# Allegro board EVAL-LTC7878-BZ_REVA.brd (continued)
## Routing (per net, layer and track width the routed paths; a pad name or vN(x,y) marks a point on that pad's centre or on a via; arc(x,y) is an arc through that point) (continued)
INTVCC_1: length 46.6
  TOP w0.254: v2(95.5,255.14) 95.81,255.14 R27.2 ; C21.1 v2(91.06,259.08) 91.19,259.21 91.19,260.22 91.97,261.01 U1.9 ; R26.2 106.05,259.52 106.05,259.84 v2(106.17,259.97) 106.06,260.08 106.06,260.44 R25.2 ; v2(78.87,258.32) TP14.1
  LAYER_6 w0.254: v2(78.87,258.32) 83.63,253.56 91.12,253.56 92.17,254.6 92.17,255.14 ; v2(106.17,259.97) 106.17,259.71 104.9,258.44 95,258.44 94.74,258.7 91.82,258.7 91.44,259.08 v2(91.06,259.08) 91.06,256.67 92.17,255.55 92.17,255.14 ; 92.17,255.14 v2(95.5,255.14)
INTVCC_2: length 47.1
  TOP w0.254: R57.2 95.81,194.18 v2(95.5,194.18) ; R55.2 106.06,199.48 106.06,199.12 v2(106.17,199.01) 106.05,198.88 106.05,198.56 R56.2 ; C54.1 v2(91.06,198.12) 91.19,198.25 91.19,199.39 91.84,200.05 U2.9 ; v2(78.87,197.36) TP39.1
  LAYER_6 w0.254: 91.95,194.18 91.95,194.56 91.06,195.45 v2(91.06,198.12) 91.82,198.12 92.2,197.74 94.61,197.74 94.93,197.42 104.97,197.42 106.17,198.63 v2(106.17,199.01) ; 91.95,194.18 91.95,193.55 90.68,192.28 83.95,192.28 v2(78.87,197.36) ; 91.95,194.18 v2(95.5,194.18)
INTVCC_3: length 46.9
  TOP w0.254: C87.1 v2(91.06,137.16) 91.06,137.35 91.19,137.48 91.19,138.43 91.84,139.09 U3.9 ; R91.2 106.06,138.52 106.06,138.16 v2(106.17,138.05) 106.05,137.92 106.05,137.6 R92.2 ; v2(78.87,136.4) TP48.1 ; v2(95.5,133.22) 95.81,133.22 R93.2
  LAYER_6 w0.254: v2(95.5,133.22) 91.95,133.22 ; 91.95,133.22 91.95,132.72 90.81,131.57 83.69,131.57 v2(78.87,136.4) ; 91.95,133.22 91.95,133.86 91.06,134.75 v2(91.06,137.16) 91.69,137.16 92.08,136.78 94.61,136.78 94.87,136.53 105.28,136.53 106.17,137.41 v2(106.17,138.05)
INTVCC_4: length 46.3
  TOP w0.254: v2(78.87,75.44) TP65.1 ; R125.2 106.05,76.64 106.05,76.96 v2(106.17,77.09) 106.06,77.2 106.06,77.56 R124.2 ; R126.2 95.81,72.26 v2(95.5,72.26) ; C120.1 v2(91.06,76.2) 91.06,76.26 91.19,76.39 91.19,77.47 91.84,78.13 U4.9
  LAYER_6 w0.254: 91.95,72.26 v2(95.5,72.26) ; 91.95,72.26 91.95,72.64 91.06,73.53 v2(91.06,76.2) 91.57,76.2 91.95,75.82 94.61,75.82 94.87,75.56 105.09,75.56 106.17,76.64 v2(106.17,77.09) ; 91.95,72.26 91.95,71.75 91.31,71.12 83.19,71.12 v2(78.87,75.44)
INTVCC_5: length 46.9
  TOP w0.254: C153.1 v2(91.06,15.24) 91.06,15.43 91.19,15.56 91.19,16.51 91.84,17.17 U5.9 ; R158.2 106.05,15.68 106.05,16 v2(106.17,16.13) 106.06,16.24 106.06,16.6 R157.2 ; v2(95.5,11.3) 95.81,11.3 R159.2 ; v2(78.87,14.48) TP82.1
  LAYER_6 w0.254: v2(95.5,11.3) 91.95,11.3 ; 91.95,11.3 91.95,10.79 90.61,9.46 83.88,9.46 v2(78.87,14.48) ; 91.95,11.3 91.95,11.75 91.06,12.64 v2(91.06,15.24) 92.08,15.24 92.33,14.99 94.49,14.99 94.87,14.61 105.09,14.61 106.17,15.68 v2(106.17,16.13)
ITH_1: length 27.3
  TOP w0.254: U1.22 98.27,258.09 99.06,257.3 v2(99.06,257.05) C14.1 ; v2(115.44,252.73) TP10.1 R4.1 ; R12.1 R11.1 98.04,255.37 99.06,256.39
  LAYER_6 w0.254: v2(99.06,257.05) 103.38,252.73 v2(115.44,252.73)
ITH_2: length 101.7
  TOP w0.254: 99.06,195.43 98.04,194.41 R41.1 R42.1 ; C47.1 v2(99.06,196.09) 99.06,196.34 98.27,197.13 U2.22 ; R174.1 TP35.1 v2(115.44,191.77) ; R4.2 v2(121.16,252.73)
  LAYER_5 w0.254: v2(115.44,191.77) 115.44,194.56 132.72,211.84 132.72,235.08 120.14,247.65 120.14,251.71 v2(121.16,252.73)
  LAYER_6 w0.254: v2(115.44,191.77) 103.38,191.77 v2(99.06,196.09)
ITH_3: length 106.9
  TOP w0.254: R174.2 v2(121.16,191.77) ; 99.06,134.47 98.04,133.45 R77.1 R78.1 ; C80.1 v2(99.06,135.13) 99.06,135.38 98.27,136.17 U3.22 ; R179.1 TP27.1 v2(115.44,130.18)
  LAYER_5 w0.254: v2(121.16,191.77) 120.02,190.63 120.02,186.31 132.72,173.61 132.72,154.18 126.75,148.21 119.51,148.21 116.59,145.29 116.59,134.62 115.44,133.48 v2(115.44,130.18)
  LAYER_6 w0.254: v2(115.44,130.18) 104.01,130.18 v2(99.06,135.13)
ITH_4: length 101.8
  TOP w0.254: C113.1 v2(99.06,74.17) 99.06,74.42 98.27,75.21 U4.22 ; R111.1 R110.1 98.04,72.49 99.06,73.51 ; v2(115.44,69.22) TP61.1 R184.1 ; R179.2 v2(121.16,130.18)
  LAYER_5 w0.254: v2(115.44,69.22) 115.44,72.64 116.46,73.66 116.46,74.93 132.72,91.19 132.72,112.27 120.27,124.71 120.27,125.98 121.16,126.87 v2(121.16,130.18)
  LAYER_6 w0.254: v2(115.44,69.22) 104.01,69.22 v2(99.06,74.17)
ITH_5: length 96
  TOP w0.254: U5.22 98.27,14.25 99.06,13.46 v2(99.06,13.21) C146.1 ; R144.1 R143.1 98.04,11.53 99.06,12.55 ; TP78.1 v2(115.44,10.16) ; R184.2 v2(121.16,69.22)
  LAYER_5 w0.254: v2(121.16,69.22) 121.16,66.29 120.14,65.28 120.14,63.75 132.72,51.18 132.72,30.61 115.44,13.34 v2(115.44,10.16)
  LAYER_6 w0.254: v2(115.44,10.16) 102.11,10.16 v2(99.06,13.21)
OUT1: length 174.5
  TOP w0.254: v2(104.46,262.32) 104.27,262.51 R1.1 ; U7.5 134.75,136.39 v2(134.75,136.4)
  LAYER_5 w0.254: v2(104.46,262.32) 107.25,262.32 107.82,261.75 121.79,261.75 140.97,242.57 140.97,156.21 134.24,149.48 134.24,144.27 133.1,143.13 126.49,143.13 122.78,139.42 JP5.8
  LAYER_6 w0.254: JP5.8 131.73,139.42 v2(134.75,136.4)
OUT2: length 97.2
  TOP w0.254: v2(104.46,201.36) 104.27,201.55 R171.1 ; U7.6 136.77,136.89 v2(137.54,137.67)
  LAYER_4 w0.254: v2(104.46,201.36) 117.67,201.36 137.92,181.1 142.49,181.1 144.78,178.82 144.78,144.27 138.18,137.67 v2(137.54,137.67)
OUT3: length 37.9
  TOP w0.254: U7.7 133.2,137.39 v2(132.72,136.91) ; v2(104.46,140.4) 104.27,140.59 R176.1
  LAYER_4 w0.254: v2(132.72,136.91) 131.7,136.91 131.44,136.65 131.44,134.49 130.3,133.35 124.71,133.35 121.16,136.91 113.79,136.91 110.3,140.4 v2(104.46,140.4)
OUT4: length 95.1
  TOP w0.254: R181.1 104.27,79.63 v2(104.46,79.44) ; v2(134.11,138.68) 134.9,137.89 U7.8
  LAYER_4 w0.254: v2(104.46,79.44) 111.44,79.44 126.62,94.61 139.57,94.61 142.11,97.16 142.11,128.65 139.32,131.44 135.64,131.44 133.73,133.35 133.73,138.3 v2(134.11,138.68)
OUT5: length 152.6
  TOP w0.254: v2(104.46,18.48) 104.27,18.67 R186.1 ; U7.9 v2(130.24,137.89)
  LAYER_4 w0.254: v2(104.46,18.48) 111.19,18.48 128.02,35.31 128.02,39.5 129.41,40.89 129.41,50.67 143.19,64.45 143.19,129.41 137.73,134.87 136.91,134.87 135.76,136.02 135.76,138.94 134.87,139.83 132.18,139.83 v2(130.24,137.89)
RUN_1: length 90.3
  TOP w0.254: R2.1 87.07,257.99 v1(87,258.06) ; U1.10 92.23,260.5 91.69,259.97 91.69,258.95 90.73,257.99 C13.1
  LAYER_4 w0.254: TP5.1 7.49,266.83 68.71,266.83 74.55,260.99 v2(78.17,260.99)
  LAYER_6 w0.254: v1(87,258.06) 84.07,260.99 v2(78.17,260.99)
RUN_2: length 177.2
  TOP w0.254: 87.5,256.26 v1(87.5,256.29) R2.2 ; C46.1 90.73,197.03 91.69,197.99 91.69,199.14 92.1,199.54 U2.10 ; v1(87,197.1) 87.07,197.03 R172.1
  LAYER_4 w0.254: TP30.1 8.45,222.88 31.31,200.03 v2(78.1,200.03)
  LAYER_5 w0.254: v1(87.5,256.29) 85.34,256.29 83.82,254.76 83.82,249.94 66.8,232.92 66.8,212.98 82.68,197.1 v1(87,197.1)
  LAYER_6 w0.254: v1(87,197.1) 84.07,200.03 v2(78.1,200.03)
RUN_3: length 186.9
  TOP w0.254: v1(87,136.14) 87.07,136.07 R177.1 ; R172.2 v1(87.5,195.33) 87.5,195.3 ; U3.10 92.17,138.58 91.69,138.11 91.69,137.03 91.09,136.43 90.91,136.43 C79.1
  LAYER_4 w0.254: v2(78.11,139.06) 49.78,139.06 9.4,98.68 7.87,98.68 TP2.1
  LAYER_5 w0.254: v1(87,136.14) 82.55,136.14 66.8,151.89 66.8,171.2 83.95,188.34 83.95,194.44 84.84,195.33 v1(87.5,195.33)
  LAYER_6 w0.254: v1(87,136.14) 87,138.05 85.98,139.06 v2(78.11,139.06)
RUN_4: length 173.9
  TOP w0.254: R182.1 87.07,75.11 v1(87,75.18) ; U4.10 92.1,77.62 91.69,77.22 91.69,76.07 90.73,75.11 C112.1 ; R177.2 v1(87.5,134.37) 87.5,134.34
  LAYER_4 w0.254: TP56.1 7.11,62.99 15.37,62.99 30.48,78.11 v2(78.11,78.11)
  LAYER_5 w0.254: v1(87,75.18) 82.55,75.18 66.8,90.93 66.8,114.43 86.74,134.37 v1(87.5,134.37)
  LAYER_6 w0.254: v2(78.11,78.11) 84.07,78.11 v1(87,75.18)
RUN_5: length 174.2
  TOP w0.254: 87.5,73.38 v1(87.5,73.41) R182.2 ; U5.10 92.1,16.66 91.69,16.26 91.69,15.11 91.06,14.48 90.81,14.48 90.55,14.22 C145.1 ; v1(87.76,14.1) 88.46,14.1 R138.2
  LAYER_4 w0.254: TP73.1 63.25,27.94 74.04,17.14 v2(78.17,17.14)
  LAYER_5 w0.254: v1(87.76,14.1) 82.68,14.1 66.8,29.97 66.8,50.29 83.95,67.44 83.95,71.88 85.47,73.41 v1(87.5,73.41)
  LAYER_6 w0.254: v1(87.76,14.1) 84.71,17.14 v2(78.17,17.14)
SS_1: length 29.6
  TOP w0.254: R3.1 TP9.1 v2(115.44,248.28) ; C11.1 v2(97.03,257.05) 97.03,257.56 97.27,257.8 U1.20
  LAYER_6 w0.254: v2(97.03,257.05) 98.04,256.03 98.04,254.13 103.89,248.28 v2(115.44,248.28)
SS_2: length 104.7
  TOP w0.254: R3.2 v2(121.16,248.28) ; C44.1 v2(97.03,196.09) 97.03,196.6 97.27,196.84 U2.20 ; v2(115.44,186.69) TP34.1 R173.1
  LAYER_5 w0.254: v2(115.44,186.69) 115.44,190.25 116.59,191.39 116.59,194.06 133.73,211.2 133.73,235.71 v2(121.16,248.28)
  LAYER_6 w0.254: v2(115.44,186.69) 104.78,186.69 98.04,193.42 98.04,195.07 v2(97.03,196.09)
SS_3: length 109.3
  TOP w0.254: U3.20 97.27,135.88 97.03,135.64 v2(97.03,135.13) C77.1 ; R178.1 TP26.1 v2(115.44,125.09) ; R173.2 v2(121.16,186.69)
  LAYER_5 w0.254: v2(121.16,186.69) 133.73,174.12 133.73,153.67 127.25,147.19 119.89,147.19 117.73,145.03 117.73,134.24 116.59,133.1 116.59,129.67 115.44,128.52 v2(115.44,125.09)
  LAYER_6 w0.254: v2(97.03,135.13) 98.04,134.11 98.04,132.46 105.41,125.09 v2(115.44,125.09)
SS_4: length 104.7
  TOP w0.254: C110.1 v2(97.03,74.17) 97.03,74.68 97.27,74.92 U4.20 ; v2(115.44,64.14) TP60.1 R183.1 ; R178.2 v2(121.16,125.09)
  LAYER_5 w0.254: v2(121.16,125.09) 121.41,125.09 133.73,112.78 133.73,90.81 117.47,74.55 117.47,73.28 116.46,72.26 116.46,68.96 115.44,67.94 v2(115.44,64.14)
  LAYER_6 w0.254: v2(115.44,64.14) 105.03,64.14 98.04,71.12 98.04,73.15 v2(97.03,74.17)
SS_5: length 98.5
  TOP w0.254: C143.1 v2(97.03,13.21) 97.03,13.72 97.27,13.96 U5.20 ; TP77.1 v2(115.44,5.08) ; R183.2 v2(121.16,64.14)
  LAYER_5 w0.254: v2(115.44,5.08) 115.44,8.64 116.59,9.78 116.59,12.95 133.73,30.1 133.73,51.56 v2(121.16,64.14)
  LAYER_6 w0.254: v2(97.03,13.21) 98.04,12.19 98.04,10.29 103.25,5.08 v2(115.44,5.08)
SYNC_1: length 83.1
  TOP w0.254: U1.30 101.48,262.01 v2(101.79,262.32) 101.98,262.51 R1.2
  LAYER_4 w0.254: TP7.1 177.16,265.43 v2(115.19,265.43)
  LAYER_6 w0.254: v2(101.79,262.32) 103.12,263.65 106.87,263.65 107.7,264.48 114.24,264.48 v2(115.19,265.43)
SYNC_2: length 90.6
  TOP w0.254: U2.30 101.48,201.05 v2(101.79,201.36) 101.98,201.55 R171.2
  LAYER_4 w0.254: TP32.1 173.23,216.41 130.24,216.41 120.04,206.21 v2(120.04,204.47)
  LAYER_6 w0.254: v2(120.04,204.47) 119.21,203.64 107.7,203.64 106.81,202.76 103.19,202.76 v2(101.79,201.36)
SYNC_3: length 100.2
  TOP w0.254: U3.30 101.48,140.09 v2(101.79,140.4) 101.98,140.59 R176.2
  LAYER_4 w0.254: v2(144.4,131.19) 144.91,131.19 TP23.1
  LAYER_6 w0.254: v2(101.79,140.4) 102.04,140.4 103.5,141.86 109.98,141.86 114.05,137.79 120.14,137.79 126.75,131.19 v2(144.4,131.19)
SYNC_4: length 89.3
  TOP w0.254: U4.30 101.48,79.13 v2(101.79,79.44) 101.98,79.63 R181.2
  LAYER_5 w0.254: v2(124.33,78.61) 162.56,78.61 TP58.1
  LAYER_6 w0.254: v2(124.33,78.61) 117.54,78.61 115.32,80.84 103.19,80.84 v2(101.79,79.44)
SYNC_5: length 84.6
  TOP w0.254: U5.30 101.48,18.17 v2(101.79,18.48) 101.98,18.67 R186.2
  LAYER_4 w0.254: TP75.1 123.07,27.81 v2(116.85,21.59)
  LAYER_6 w0.254: v2(116.85,21.59) 108.84,21.59 107.06,19.81 103.12,19.81 v2(101.79,18.48)
UNNAMED_1_ADLTC7878V2_I139_BG1: length 27.7
  TOP w0.254: v1(92.84,265.81) 92.84,265.01 U1.1 ; R10.2 v1(72.64,276.73)
  LAYER_4 w0.508: v1(92.84,265.81) 92.33,266.32 92.33,268.1 89.15,271.27 77.47,271.27 72.64,276.1 v1(72.64,276.73)
UNNAMED_1_ADLTC7878V2_I139_BG2: length 38.1
  TOP w0.254: R28.2 v1(106.81,276.73) ; U1.12 92.94,259.5 92.84,259.4
  TOP w0.381: 92.84,259.4 v1(92.84,257.68)
  LAYER_4 w0.508: v1(92.84,257.68) 92.84,256.16 95.38,253.62 99.69,253.62 102.87,256.79 102.87,265.43 106.81,269.37 v1(106.81,276.73)
UNNAMED_1_ADLTC7878V2_I139_BOOST1: length 2
  TOP w0.254: C16.1 94.77,267.12 U1.46
UNNAMED_1_ADLTC7878V2_I139_BOOST2: length 2.7
  TOP w0.254: C19.2 94.77,257.51 U1.15
UNNAMED_1_ADLTC7878V2_I139_CSN: length 6.4
  TOP w0.254: TP11.1 103.76,266.64 R29.1 102.62,266.57 100.55,264.5 U1.35
UNNAMED_1_ADLTC7878V2_I139_CSP: length 2.8
  TOP w0.254: TP16.1 101.85,264.92 100.94,264.01 U1.34
UNNAMED_1_ADLTC7878V2_I139_EXTVCC: length 16.1
  TOP w0.254: TP12.1 v2(78.99,263.14) ; U1.8 90.19,261.5 C20.1
  LAYER_6 w0.254: v2(91,262) 88.65,262 87.5,263.14 v2(78.99,263.14)
UNNAMED_1_ADLTC7878V2_I139_FREQ: length 2.8
  TOP w0.254: R18.1 101.98,261.49 101.49,261.01 U1.28
UNNAMED_1_ADLTC7878V2_I139_ISNSD: length 3.9
  TOP w0.254: U1.43 96.27,266.57 95.76,267.08 95.76,268.22 v2(95.5,268.48) 95.5,268.8 C17.1
  BOTTOM w0.254: C17.1 95.5,268.8 v2(95.5,268.48)
UNNAMED_1_ADLTC7878V2_I139_ISNSN: length 7.3
  TOP w0.254: C18.2 98.22,268.68 97.79,269.11 R16.2 R23.2 ; C18.2 v2(97.66,267.72) ; C18.2 97.27,266.76 U1.41
  BOTTOM w0.254: 96.51,267.84 R21.2 96.7,267.72 v2(97.66,267.72)
UNNAMED_1_ADLTC7878V2_I139_ISNSP: length 6.3
  TOP w0.254: 96.6,268.84 C18.1 96.77,267.54 U1.42 ; 96.6,268.84 96.7,268.73 v2(97.03,268.73) ; 96.6,268.84 C17.2 96.58,269.89 R19.2 R13.2
  BOTTOM w0.254: C17.2 96.7,268.73 v2(97.03,268.73)
UNNAMED_1_ADLTC7878V2_I139_ITHB: length 2.4
  TOP w0.254: R11.2 98.04,257.56 97.77,257.83 U1.21
UNNAMED_1_ADLTC7878V2_I139_MODE: length 6.1
  TOP w0.254: R22.1 v2(101.79,259.46) 101.26,259.46 100.71,260.01 U1.26 ; R26.1 v2(104.55,259.46)
  LAYER_6 w0.254: v2(101.79,259.46) 101.85,259.4 104.48,259.4 v2(104.55,259.46)
UNNAMED_1_ADLTC7878V2_I139_PGOOD: length 24.9
  TOP w0.254: U1.19 96.77,258.06 96.01,257.3 v2(96.01,257.05) R27.1 ; v2(78.87,254.63) TP15.1
  LAYER_6 w0.254: v2(96.01,257.05) 96.01,256.6 96.27,256.35 96.27,255.02 93.73,252.48 81.03,252.48 v2(78.87,254.63)
UNNAMED_1_ADLTC7878V2_I139_PHASMD: length 6.2
  TOP w0.254: 101.88,260.5 102.08,260.5 ; 101.88,260.5 101.85,260.48 ; 101.88,260.5 U1.27 ; 101.85,260.48 v2(101.79,260.48) ; 101.85,260.48 R24.1 ; R25.1 v2(104.55,260.48)
  LAYER_6 w0.254: v2(104.55,260.48) 104.48,260.54 101.85,260.54 v2(101.79,260.48)
UNNAMED_1_ADLTC7878V2_I139_SETCUR: length 3
  TOP w0.254: R20.1 102.11,263.52 101.09,262.5 U1.31
UNNAMED_1_ADLTC7878V2_I139_SW1: length 48.9
  TOP w0.254: R13.1 95.07,271.07 95,271.14 v1(94.87,271.14) ; R14.1 v1(82.55,281.05) ; C16.2 95.27,267.75 U1.45 ; C16.2 93.92,268.66 93.85,268.73 v1(93.6,268.73) ; C16.2 94.37,268.66
  LAYER_4 w0.508: v1(93.6,268.73) 89.28,273.05 86.36,273.05 80.01,279.4 80.01,283.21 79.5,283.72 v4(78.61,283.72)
  LAYER_6 w0.254: v1(82.55,281.05) 82.93,280.67 82.93,275.59 83.95,274.57 91.95,274.57 94.87,271.65 v1(94.87,271.14)
  vias: v4(74.8,283.72) v4(74.8,282.45) v4(74.8,281.18) v4(74.8,279.91) v4(76.07,283.72) v4(76.07,282.45) v4(76.07,281.18) v4(76.07,279.91) v4(77.34,283.72) v4(77.34,282.45) v4(77.34,281.18) v4(77.34,279.91) v4(78.61,282.45) v4(78.61,281.18) v4(78.61,279.91)
UNNAMED_1_ADLTC7878V2_I139_SW2: length 51.9
  TOP w0.254: U1.16 95.27,256.89 C19.1 ; L1.2 98.7,283.23 v1(98.68,283.21) ; R23.1 v1(99.06,271.78)
  TOP w0.508: C19.1 94.92,256.09 v1(94.87,256.03)
  LAYER_4 w0.508: v4(108.58,280.67) 107.89,280.67 104.65,277.43 104.65,269.88 99.89,265.11 99.89,260.03 98.17,258.32 95.76,258.32 94.87,257.43 v1(94.87,256.03)
  LAYER_6 w0.254: v1(98.68,283.21) 96.77,281.31 96.77,277.11 98.04,275.84 98.04,273.18 99.06,272.16 v1(99.06,271.78)
  vias: v3(99.19,280.16) v3(99.19,279.4) v3(99.95,280.16) v3(99.95,279.4) v3(100.71,280.16) v3(100.71,279.4) v3(101.47,280.16) v3(101.47,279.4) v3(102.23,280.16) v3(102.23,279.4) v4(108.58,284.48) v4(108.58,283.21) v4(108.58,281.94) v4(109.86,284.48) v4(109.86,283.21) v4(109.86,281.94) v4(109.86,280.67) v4(111.12,284.48) v4(111.12,283.21) v4(111.12,281.94) v4(111.12,280.67) v4(112.39,284.48) v4(112.39,283.21) v4(112.39,281.94) v4(112.39,280.67)
UNNAMED_1_ADLTC7878V2_I139_TG1: length 30.7
  TOP w0.254: v1(93.6,266.7) 93.85,266.7 94.27,266.28 U1.47
  LAYER_4 w0.508: v1(93.6,266.7) 94.49,267.59 94.49,269.11 89.53,274.07 86.74,274.07 80.9,279.91 80.9,286.89 v1(79.88,287.91)
UNNAMED_1_ADLTC7878V2_I139_TG2: length 43.9
  TOP w0.254: R30.2 v1(114.05,287.91) ; v1(93.98,257.68) 94.27,257.97 U1.14
  LAYER_4 w0.508: v1(93.98,257.68) 95.5,259.21 97.79,259.21 99.06,260.48 99.06,265.56 103.76,270.26 103.76,277.88 107.19,281.31 107.19,284.86 108.2,285.88 112.01,285.88 v1(114.05,287.91)
UNNAMED_1_ADLTC7878V2_I139_VIN: length 3.3
  TOP w0.254: C12.1 91.19,264.39 92.08,263.5 U1.4
UNNAMED_1_ADLTC7878V2_I139_VOUT: length 19.2
  TOP w0.254: R71.1 100.13,268.17 100.08,268.22 v1(99.69,268.22) 99.19,267.72 99.19,266.83 98.77,266.41 U1.38 ; R70.2 v2(88.77,260.1)
  LAYER_4 w0.254: v1(99.69,268.22) 97.79,266.32 95.38,266.32 92.33,263.27 92.33,261.87 91.31,260.86 89.53,260.86 v2(88.77,260.1)
UNNAMED_1_CAP_I38_N1: length 1
  TOP w0.254: R12.2 C15.1
UNNAMED_1_CAP_I100_N2: length 2
  TOP w0.254: R32.1 106.68,267.14 TP13.1
UNNAMED_1_IND_I92_N1: length 41.1
  TOP w0.254: R14.2 v1(83.82,281.05) ; R16.1 v1(97.79,271.78) ; v1(94.36,283.21) 94.34,283.23 L1.1 ; R19.1 v1(96.52,271.65)
  LAYER_6 w0.254: v1(94.36,283.21) 96.27,281.31 96.27,276.86 97.54,275.59 97.54,273.18 96.52,272.16 v1(96.52,271.65) ; v1(83.82,281.05) 83.44,280.67 83.44,275.84 84.2,275.08 92.2,275.08 95.38,271.91 95.38,271.53 96.01,270.89 97.28,270.89 97.79,271.4 v1(97.79,271.78)
  vias: v3(90.68,280.16) v3(90.68,279.4) v3(91.44,280.16) v3(91.44,279.4) v3(92.2,280.16) v3(92.2,279.4) v3(92.96,280.16) v3(92.96,279.4) v3(93.73,280.16) v3(93.73,279.4)
UNNAMED_1_NCTESTPAD_I113_N1: length 5.3
  TOP w0.254: R35.1 R34.2
  TOP w0.381: TP20.1 106.68,255.97 105.03,257.62 105.03,258.26 104.97,258.32 R34.2
UNNAMED_1_RES_I72_N1: length 7.7
  TOP w0.254: v1(79.25,286.26) 78.86,285.87 78.37,285.87
  LAYER_6 w0.508: v1(73.66,286.26) v1(79.25,286.26)
  BOTTOM w0.254: v1(73.66,286.26) 74.05,285.87 74.53,285.87
UNNAMED_1_RES_I73_N1: length 7.8
  TOP w0.254: v1(73.15,279.02) 73.15,279.38 72.61,279.92
  LAYER_6 w0.508: v1(73.15,284.61) v1(73.15,279.02)
  BOTTOM w0.254: v1(73.15,284.61) 72.61,284.06 72.61,283.76
UNNAMED_1_RES_I87_N1: length 7.9
  TOP w0.254: M3.4 112.99,278.68 v1(113.28,278.38)
  LAYER_6 w0.508: v1(107.57,278.38) v1(113.28,278.38)
  BOTTOM w0.254: M7.4 107.86,278.68 v1(107.57,278.38)
UNNAMED_1_RES_I115_N1: length 8.2
  TOP w0.254: M4.4 114.44,280.32 114.05,279.92 v1(114.05,279.78)
  LAYER_6 w0.508: v1(114.05,285.62) v1(114.05,279.78)
  BOTTOM w0.254: M8.4 114.44,285.23 v1(114.05,285.62)
UNNAMED_2_ADLTC7878V2_I124_BG1: length 27.4
  TOP w0.254: R40.2 v1(72.64,215.77) ; U2.1 92.84,204.05 v1(92.84,204.85)
  LAYER_4 w0.508: v1(72.64,215.77) 77.85,210.57 88.9,210.57 92.33,207.14 92.33,205.36 v1(92.84,204.85)
UNNAMED_2_ADLTC7878V2_I124_BG2: length 38.3
  TOP w0.254: 92.84,198.5 92.88,198.54 U2.12 ; R58.2 v1(106.81,215.77)
  TOP w0.381: v1(92.84,196.72) 92.84,198.5
  LAYER_4 w0.508: v1(106.81,215.77) 106.81,208.28 102.87,204.34 102.87,195.58 99.95,192.66 95.38,192.66 92.84,195.2 v1(92.84,196.72)
UNNAMED_2_ADLTC7878V2_I124_BOOST1: length 2
  TOP w0.254: U2.46 94.77,206.16 C49.1
UNNAMED_2_ADLTC7878V2_I124_BOOST2: length 2.7
  TOP w0.254: C52.2 94.77,196.55 U2.15
UNNAMED_2_ADLTC7878V2_I124_CSN: length 6.4
  TOP w0.254: U2.35 100.55,203.54 102.49,205.49 103.7,205.49 R59.1 103.83,207.19 TP36.1
UNNAMED_2_ADLTC7878V2_I124_CSP: length 2.9
  TOP w0.254: TP41.1 102.23,203.71 101.47,203.71 100.81,203.05 U2.34
UNNAMED_2_ADLTC7878V2_I124_EXTVCC: length 16.1
  TOP w0.254: C53.1 90.19,200.54 U2.8 ; TP37.1 v2(78.99,202.18)
  LAYER_6 w0.254: v2(78.99,202.18) 87.25,202.18 88.39,201.04 v2(91,201.04)
UNNAMED_2_ADLTC7878V2_I124_FREQ: length 2.8
  TOP w0.254: U2.28 101.49,200.05 101.98,200.53 R48.1
UNNAMED_2_ADLTC7878V2_I124_ISNSD: length 3.9
  TOP w0.254: C50.1 95.5,207.84 v2(95.5,207.52) 95.76,207.26 95.76,206.12 96.27,205.61 U2.43
  BOTTOM w0.254: C50.1 95.5,207.84 v2(95.5,207.52)
UNNAMED_2_ADLTC7878V2_I124_ISNSN: length 7.3
  TOP w0.254: R53.2 R46.2 97.79,208.15 98.22,207.72 C51.2 ; C51.2 97.27,205.8 U2.41 ; C51.2 v2(97.66,206.76)
  BOTTOM w0.254: 96.51,206.88 R51.2 97.54,206.88 v2(97.66,206.76)
UNNAMED_2_ADLTC7878V2_I124_ISNSP: length 6.3
  TOP w0.254: 96.6,207.88 C51.1 96.77,206.58 U2.42 ; 96.6,207.88 96.7,207.77 v2(97.03,207.77) ; 96.6,207.88 C50.2 96.58,208.93 R49.2 R43.2
  BOTTOM w0.254: C50.2 96.7,207.77 v2(97.03,207.77)
UNNAMED_2_ADLTC7878V2_I124_ITHB: length 2.4
  TOP w0.254: R41.2 98.04,196.6 97.77,196.87 U2.21
UNNAMED_2_ADLTC7878V2_I124_MODE: length 6.1
  TOP w0.254: U2.26 100.71,199.05 101.26,198.5 v2(101.79,198.5) R52.1 ; R56.1 v2(104.55,198.5)
  LAYER_6 w0.254: v2(104.55,198.5) 104.48,198.44 101.85,198.44 v2(101.79,198.5)
UNNAMED_2_ADLTC7878V2_I124_PGOOD: length 25.4
  TOP w0.254: R57.1 v2(96.01,196.09) 96.01,196.34 96.77,197.1 U2.19 ; v2(78.87,193.68) TP40.1
  LAYER_6 w0.254: v2(96.01,196.09) 96.01,195.71 96.39,195.33 96.39,194.18 93.22,191.01 81.53,191.01 v2(78.87,193.68)
UNNAMED_2_ADLTC7878V2_I124_PHASMD: length 6.2
  TOP w0.254: 102.08,199.54 101.82,199.54 ; 101.82,199.54 U2.27 ; 101.82,199.54 v2(101.79,199.52) R54.1 ; R55.1 v2(104.55,199.52)
  LAYER_6 w0.254: v2(104.55,199.52) 104.48,199.58 101.85,199.58 v2(101.79,199.52)
UNNAMED_2_ADLTC7878V2_I124_SETCUR: length 3
  TOP w0.254: U2.31 101.09,201.54 102.11,202.56 R50.1
UNNAMED_2_ADLTC7878V2_I124_SW1: length 48.9
  TOP w0.254: C49.2 95.27,206.79 U2.45 ; C49.2 93.92,207.7 93.85,207.77 v1(93.6,207.77) ; C49.2 94.37,207.7 ; R43.1 95.07,210.11 95,210.19 v1(94.87,210.19) ; R44.1 v1(82.55,220.09)
  LAYER_4 w0.508: v1(93.6,207.77) 89.28,212.09 86.36,212.09 79.88,218.57 79.88,222.38 79.5,222.76 v4(78.61,222.76)
  LAYER_6 w0.254: v1(94.87,210.19) 94.87,210.76 94.04,211.58 85.98,211.58 82.93,214.63 82.93,219.71 v1(82.55,220.09)
  vias: v4(74.8,222.76) v4(74.8,221.49) v4(74.8,220.22) v4(74.8,218.95) v4(76.07,222.76) v4(76.07,221.49) v4(76.07,220.22) v4(76.07,218.95) v4(77.34,222.76) v4(77.34,221.49) v4(77.34,220.22) v4(77.34,218.95) v4(78.61,221.49) v4(78.61,220.22) v4(78.61,218.95)
UNNAMED_2_ADLTC7878V2_I124_SW2: length 51.9
  TOP w0.254: U2.16 95.27,195.93 C52.1 ; L2.2 98.7,222.27 v1(98.68,222.25) ; R53.1 v1(99.06,210.82)
  TOP w0.508: v1(94.87,195.07) 94.92,195.13 C52.1
  LAYER_4 w0.508: v1(94.87,195.07) 94.87,196.47 95.76,197.36 98.17,197.36 99.89,199.07 99.89,204.03 104.65,208.79 104.65,216.47 107.89,219.71 v4(108.58,219.71)
  LAYER_6 w0.254: v1(98.68,222.25) 96.77,220.34 96.77,216.15 98.04,214.88 98.04,212.22 99.06,211.2 v1(99.06,210.82)
  vias: v3(99.19,219.2) v3(99.19,218.44) v3(99.95,219.2) v3(99.95,218.44) v3(100.71,219.2) v3(100.71,218.44) v3(101.47,219.2) v3(101.47,218.44) v3(102.23,219.2) v3(102.23,218.44) v4(108.58,223.52) v4(108.58,222.25) v4(108.58,220.98) v4(109.86,223.52) v4(109.86,222.25) v4(109.86,220.98) v4(109.86,219.71) v4(111.12,223.52) v4(111.12,222.25) v4(111.12,220.98) v4(111.12,219.71) v4(112.39,223.52) v4(112.39,222.25) v4(112.39,220.98) v4(112.39,219.71)
UNNAMED_2_ADLTC7878V2_I124_TG1: length 30.7
  TOP w0.254: v1(93.6,205.74) 93.85,205.74 94.27,205.32 U2.47
  LAYER_4 w0.508: v1(93.6,205.74) 93.6,206.25 94.49,207.14 94.49,208.15 89.66,212.98 86.87,212.98 80.9,218.95 80.9,225.93 v1(79.88,226.95)
UNNAMED_2_ADLTC7878V2_I124_TG2: length 44.1
  TOP w0.254: v1(93.98,196.72) 93.98,196.98 94.27,197.27 U2.14 ; R60.2 v1(114.05,226.95)
  LAYER_4 w0.508: v1(93.98,196.72) 93.98,196.98 95.25,198.25 97.79,198.25 99.06,199.52 99.06,204.47 103.76,209.17 103.76,216.92 107.19,220.34 107.19,223.9 108.2,224.92 112.01,224.92 v1(114.05,226.95)
UNNAMED_2_ADLTC7878V2_I124_VIN: length 3.3
  TOP w0.254: U2.4 92.08,202.54 91.19,203.43 C45.1
UNNAMED_2_ADLTC7878V2_I124_VOUT: length 19.2
  TOP w0.254: R67.2 v2(88.77,199.14) ; U2.38 98.77,205.45 99.19,205.87 99.19,206.76 v1(99.69,207.26) 100.08,207.26 100.13,207.21 R68.1
  LAYER_4 w0.254: v2(88.77,199.14) 89.66,200.03 91.69,200.03 92.84,201.17 92.84,202.44 95.89,205.49 97.92,205.49 v1(99.69,207.26)
UNNAMED_2_CAP_I32_N1: length 1
  TOP w0.254: R42.2 C48.1
UNNAMED_2_CAP_I92_N2: length 2
  TOP w0.254: TP38.1 106.68,206.18 R62.1
UNNAMED_2_IND_I83_N1: length 41.2
  TOP w0.254: L2.1 94.34,222.27 v1(94.36,222.25) ; R49.1 v1(96.52,210.69) ; R46.1 v1(97.79,210.82) ; R44.2 v1(83.82,220.09)
  LAYER_6 w0.254: v1(94.36,222.25) 96.27,220.34 96.27,215.9 97.54,214.63 97.54,212.22 96.52,211.2 v1(96.52,210.69) ; v1(83.82,220.09) 83.44,219.71 83.44,214.88 86.23,212.09 94.36,212.09 95.5,210.95 95.5,210.31 95.89,209.93 97.28,209.93 97.79,210.44 v1(97.79,210.82)
  vias: v3(90.68,219.2) v3(90.68,218.44) v3(91.44,219.2) v3(91.44,218.44) v3(92.2,219.2) v3(92.2,218.44) v3(92.96,219.2) v3(92.96,218.44) v3(93.73,219.2) v3(93.73,218.44)
UNNAMED_2_NCTESTPAD_I104_N1: length 5.3
  TOP w0.254: R65.1 R64.2
  TOP w0.381: R64.2 104.97,197.36 105.03,197.3 105.03,196.66 106.68,195.01 TP45.1
UNNAMED_2_RES_I63_N1: length 7.7
  TOP w0.254: v1(79.25,225.3) 78.86,224.91 78.37,224.91
  LAYER_6 w0.508: v1(73.66,225.3) v1(79.25,225.3)
  BOTTOM w0.254: 74.53,224.91 74.05,224.91 v1(73.66,225.3)
UNNAMED_2_RES_I64_N1: length 7.8
  TOP w0.254: 72.61,218.96 73.15,218.42 v1(73.15,218.06)
  LAYER_6 w0.508: v1(73.15,223.65) v1(73.15,218.06)
  BOTTOM w0.254: 72.61,222.8 72.61,223.1 v1(73.15,223.65)
UNNAMED_2_RES_I78_N1: length 7.9
  TOP w0.254: M11.4 112.99,217.72 v1(113.28,217.42)
  LAYER_6 w0.508: v1(107.57,217.42) v1(113.28,217.42)
  BOTTOM w0.254: M15.4 107.86,217.72 v1(107.57,217.42)
UNNAMED_2_RES_I106_N1: length 8.2
  TOP w0.254: M12.4 114.44,219.36 114.05,218.96 v1(114.05,218.82)
  LAYER_6 w0.508: v1(114.05,224.66) v1(114.05,218.82)
  BOTTOM w0.254: M16.4 114.44,224.27 v1(114.05,224.66)
UNNAMED_3_ADLTC7878V2_I47_BG1: length 27.7
  TOP w0.254: v1(92.84,143.89) 92.84,143.09 U3.1 ; R76.2 v1(72.64,154.81)
  LAYER_4 w0.508: v1(92.84,143.89) 92.33,144.4 92.33,146.3 89.41,149.22 77.72,149.22 72.64,154.31 v1(72.64,154.81)
UNNAMED_3_ADLTC7878V2_I47_BG2: length 38
  TOP w0.254: R95.2 v1(106.81,154.81) ; U3.12 92.88,137.58 92.84,137.54
  TOP w0.381: v1(92.84,135.76) 92.84,137.54
  LAYER_4 w0.508: v1(92.84,135.76) 92.84,134.24 95.38,131.7 99.44,131.7 102.87,135.13 102.87,143.51 106.81,147.45 v1(106.81,154.81)
UNNAMED_3_ADLTC7878V2_I47_BOOST1: length 2
  TOP w0.254: C82.1 94.77,145.2 U3.46
UNNAMED_3_ADLTC7878V2_I47_BOOST2: length 2.7
  TOP w0.254: C85.2 94.77,135.59 U3.15
UNNAMED_3_ADLTC7878V2_I47_CSN: length 6.4
  TOP w0.254: TP28.1 103.76,144.72 R96.1 102.62,144.65 100.55,142.58 U3.35
UNNAMED_3_ADLTC7878V2_I47_CSP: length 2.9
  TOP w0.254: U3.34 100.81,142.09 101.66,142.94 102.43,142.94 TP50.1
UNNAMED_3_ADLTC7878V2_I47_EXTVCC: length 16.1
  TOP w0.254: C86.1 90.19,139.58 U3.8 ; TP29.1 v2(78.99,141.22)
  LAYER_6 w0.254: v2(91,140.08) 88.39,140.08 87.25,141.22 v2(78.99,141.22)
UNNAMED_3_ADLTC7878V2_I47_FREQ: length 2.8
  TOP w0.254: R84.1 101.98,139.57 101.49,139.09 U3.28
UNNAMED_3_ADLTC7878V2_I47_ISNSD: length 3.9
  TOP w0.254: C83.1 95.5,146.88 v2(95.5,146.56) 95.76,146.3 95.76,145.16 96.27,144.65 U3.43
  BOTTOM w0.254: C83.1 95.45,146.61 v2(95.5,146.56)
UNNAMED_3_ADLTC7878V2_I47_ISNSN: length 7.3
  TOP w0.254: C84.2 97.27,144.84 U3.41 ; C84.2 98.22,146.76 97.79,147.19 R82.2 R89.2 ; C84.2 v2(97.66,145.8)
  BOTTOM w0.254: R87.2 97.54,145.92 v2(97.66,145.8)
UNNAMED_3_ADLTC7878V2_I47_ISNSP: length 6.3
  TOP w0.254: 96.6,146.92 C84.1 96.77,145.62 U3.42 ; 96.6,146.92 96.7,146.81 v2(97.03,146.81) ; 96.6,146.92 C83.2 96.58,147.97 R85.2 R79.2
  BOTTOM w0.254: v2(97.03,146.81) 96.7,146.81 C83.2
UNNAMED_3_ADLTC7878V2_I47_ITHB: length 2.4
  TOP w0.254: U3.21 97.77,135.91 98.04,135.64 R77.2
UNNAMED_3_ADLTC7878V2_I47_MODE: length 6.1
  TOP w0.254: U3.26 100.71,138.09 101.26,137.54 v2(101.79,137.54) R88.1 ; R92.1 v2(104.55,137.54)
  LAYER_6 w0.254: v2(104.55,137.54) 104.48,137.48 101.85,137.48 v2(101.79,137.54)
UNNAMED_3_ADLTC7878V2_I47_PGOOD: length 25.1
  TOP w0.254: v2(78.87,132.72) TP49.1 ; U3.19 96.77,136.14 96.01,135.38 v2(96.01,135.13) R93.1
  LAYER_6 w0.254: v2(78.87,132.72) 81.15,130.43 93.6,130.43 96.39,133.22 96.39,134.24 96.01,134.62 v2(96.01,135.13)
UNNAMED_3_ADLTC7878V2_I47_PHASMD: length 6.2
  TOP w0.254: 101.82,138.58 U3.27 ; 101.82,138.58 v2(101.79,138.56) R90.1 ; 101.82,138.58 102.08,138.58 ; R91.1 v2(104.55,138.56)
  LAYER_6 w0.254: v2(104.55,138.56) 104.48,138.62 101.85,138.62 v2(101.79,138.56)
UNNAMED_3_ADLTC7878V2_I47_SETCUR: length 3
  TOP w0.254: R86.1 102.11,141.6 101.09,140.58 U3.31
UNNAMED_3_ADLTC7878V2_I47_SW1: length 49
  TOP w0.254: C82.2 95.27,145.83 U3.45 ; C82.2 93.92,146.74 93.85,146.81 v1(93.6,146.81) ; C82.2 94.37,146.74 ; R79.1 95.07,149.15 95,149.22 v1(94.87,149.22) ; R80.1 v1(82.55,159.13)
  LAYER_4 w0.508: v4(78.61,161.8) 79.5,161.8 80.01,161.29 80.01,157.48 86.74,150.75 89.66,150.75 v1(93.6,146.81)
  LAYER_6 w0.254: v1(82.55,159.13) 82.93,158.75 82.93,153.67 83.95,152.65 92.08,152.65 94.87,149.86 v1(94.87,149.22)
  vias: v4(74.8,161.8) v4(74.8,160.53) v4(74.8,159.26) v4(74.8,157.99) v4(76.07,161.8) v4(76.07,160.53) v4(76.07,159.26) v4(76.07,157.99) v4(77.34,161.8) v4(77.34,160.53) v4(77.34,159.26) v4(77.34,157.99) v4(78.61,160.53) v4(78.61,159.26) v4(78.61,157.99)
UNNAMED_3_ADLTC7878V2_I47_SW2: length 52.2
  TOP w0.254: R89.1 v1(99.06,149.86) ; v1(98.68,161.29) 98.7,161.31 L3.2 ; U3.16 95.27,134.97 C85.1
  TOP w0.508: v1(94.87,134.11) 94.92,134.17 C85.1
  LAYER_4 w0.508: v4(108.58,158.75) 107.89,158.75 104.65,155.51 104.65,147.7 99.89,142.94 99.89,137.86 98.81,136.78 95.89,136.78 94.87,135.76 v1(94.87,134.11)
  LAYER_6 w0.254: v1(98.68,161.29) 96.77,159.38 96.77,155.19 98.04,153.92 98.04,151.13 99.06,150.11 v1(99.06,149.86)
  vias: v3(99.19,158.24) v3(99.19,157.48) v3(99.95,158.24) v3(99.95,157.48) v3(100.71,158.24) v3(100.71,157.48) v3(101.47,158.24) v3(101.47,157.48) v3(102.23,158.24) v3(102.23,157.48) v4(108.58,162.56) v4(108.58,161.29) v4(108.58,160.02) v4(109.86,162.56) v4(109.86,161.29) v4(109.86,160.02) v4(109.86,158.75) v4(111.12,162.56) v4(111.12,161.29) v4(111.12,160.02) v4(111.12,158.75) v4(112.39,162.56) v4(112.39,161.29) v4(112.39,160.02) v4(112.39,158.75)
UNNAMED_3_ADLTC7878V2_I47_TG1: length 30.8
  TOP w0.254: v1(93.6,144.78) 93.85,144.78 94.27,144.36 U3.47
  LAYER_4 w0.508: v1(93.6,144.78) 94.61,145.8 94.61,147.07 90.04,151.64 87.25,151.64 80.9,157.99 80.9,164.97 v1(79.88,165.99)
UNNAMED_3_ADLTC7878V2_I47_TG2: length 44.3
  TOP w0.254: U3.14 94.27,136.05 v1(93.98,135.76) ; R97.2 v1(114.05,165.99)
  LAYER_4 w0.508: v1(93.98,135.76) 93.98,136.14 95.5,137.67 98.42,137.67 99.06,138.3 99.06,143.38 103.76,148.08 103.76,155.96 107.19,159.38 107.19,162.94 108.2,163.96 112.01,163.96 v1(114.05,165.99)
UNNAMED_3_ADLTC7878V2_I47_VIN: length 3.3
  TOP w0.254: U3.4 92.08,141.58 91.19,142.47 C78.1
UNNAMED_3_ADLTC7878V2_I47_VOUT: length 19.2
  TOP w0.254: R98.1 100.13,146.25 100.08,146.3 v1(99.69,146.3) 99.19,145.8 99.19,144.91 98.77,144.49 U3.38 ; R94.2 v2(88.77,138.18)
  LAYER_4 w0.254: v1(99.69,146.3) 98.04,144.65 95.76,144.65 92.84,141.73 92.84,140.34 90.68,138.18 v2(88.77,138.18)
UNNAMED_3_CAP_I32_N1: length 1
  TOP w0.254: R78.2 C81.1
UNNAMED_3_CAP_I94_N2: length 2
  TOP w0.254: R100.1 106.68,145.22 TP47.1
UNNAMED_3_IND_I85_N1: length 41.2
  TOP w0.254: L3.1 94.34,161.31 v1(94.36,161.29) ; R82.1 v1(97.79,149.86) ; R80.2 v1(83.82,159.13) ; R85.1 v1(96.52,149.73)
  LAYER_6 w0.254: v1(96.52,149.73) 96.52,150.11 97.54,151.13 97.54,153.67 96.27,154.94 96.27,159.38 v1(94.36,161.29) ; v1(83.82,159.13) 83.44,158.75 83.44,153.92 84.2,153.16 92.46,153.16 95.5,150.11 95.5,149.48 96.01,148.97 97.28,148.97 97.79,149.48 v1(97.79,149.86)
  vias: v3(90.68,158.24) v3(90.68,157.48) v3(91.44,158.24) v3(91.44,157.48) v3(92.2,158.24) v3(92.2,157.48) v3(92.96,158.24) v3(92.96,157.48) v3(93.73,158.24) v3(93.73,157.48)
UNNAMED_3_NCTESTPAD_I107_N1: length 5.3
  TOP w0.254: R103.1 R102.2
  TOP w0.381: R102.2 104.97,136.4 105.03,136.34 105.03,135.7 106.68,134.05 TP54.1
UNNAMED_3_RES_I65_N1: length 7.7
  TOP w0.254: 78.37,163.95 78.86,163.95 v1(79.25,164.34)
  LAYER_6 w0.508: v1(73.66,164.34) v1(79.25,164.34)
  BOTTOM w0.254: 74.53,163.95 74.05,163.95 v1(73.66,164.34)
UNNAMED_3_RES_I66_N1: length 7.8
  TOP w0.254: v1(73.15,157.1) 73.15,157.46 72.61,158
  LAYER_6 w0.508: v1(73.15,162.69) v1(73.15,157.1)
  BOTTOM w0.254: 72.61,161.84 72.61,162.14 v1(73.15,162.69)
UNNAMED_3_RES_I80_N1: length 7.9
  TOP w0.254: v1(113.28,156.46) 112.99,156.76 M19.4
  LAYER_6 w0.508: v1(107.57,156.46) v1(113.28,156.46)
  BOTTOM w0.254: M23.4 107.86,156.76 v1(107.57,156.46)
UNNAMED_3_RES_I109_N1: length 8.2
  TOP w0.254: M20.4 114.44,158.4 114.05,158 v1(114.05,157.86)
  LAYER_6 w0.508: v1(114.05,163.7) v1(114.05,157.86)
  BOTTOM w0.254: v1(114.05,163.7) 114.44,163.31 M24.4
UNNAMED_4_ADLTC7878V2_I126_BG1: length 27.6
  TOP w0.254: v1(92.84,82.93) 92.84,82.13 U4.1 ; R109.2 v1(72.64,93.85)
  LAYER_4 w0.508: v1(92.84,82.93) 92.33,83.44 92.33,85.09 89.03,88.39 77.6,88.39 72.64,93.34 v1(72.64,93.85)
UNNAMED_4_ADLTC7878V2_I126_BG2: length 38
  TOP w0.254: R128.2 v1(106.81,93.85) ; U4.12 92.88,76.62 92.84,76.58
  TOP w0.381: v1(92.84,74.8) 92.84,76.58
  LAYER_4 w0.508: v1(92.84,74.8) 92.84,73.28 95.38,70.74 99.57,70.74 102.87,74.04 102.87,82.55 106.81,86.49 v1(106.81,93.85)
UNNAMED_4_ADLTC7878V2_I126_BOOST1: length 2
  TOP w0.254: C115.1 94.77,84.24 U4.46
UNNAMED_4_ADLTC7878V2_I126_BOOST2: length 2.7
  TOP w0.254: C118.2 94.77,74.63 U4.15
UNNAMED_4_ADLTC7878V2_I126_CSN: length 6.4
  TOP w0.254: U4.35 100.55,81.62 102.62,83.69 R129.1 103.76,83.76 TP62.1
UNNAMED_4_ADLTC7878V2_I126_CSP: length 2.9
  TOP w0.254: TP67.1 102.23,81.79 101.47,81.79 100.81,81.13 U4.34
UNNAMED_4_ADLTC7878V2_I126_EXTVCC: length 16.6
  TOP w0.254: U4.8 90.19,78.62 C119.1 ; TP63.1 v2(78.99,80.26)
  LAYER_6 w0.254: v2(78.99,80.26) 82.8,80.26 83.31,80.77 86.87,80.77 88.52,79.12 v2(91,79.12)
UNNAMED_4_ADLTC7878V2_I126_FREQ: length 2.8
  TOP w0.254: U4.28 101.49,78.13 101.98,78.61 R117.1
UNNAMED_4_ADLTC7878V2_I126_ISNSD: length 3.9
  TOP w0.254: U4.43 96.27,83.69 95.76,84.2 95.76,85.34 v2(95.5,85.6) 95.5,85.92 C116.1
  BOTTOM w0.254: C116.1 95.5,85.92 v2(95.5,85.6)
UNNAMED_4_ADLTC7878V2_I126_ISNSN: length 7.3
  TOP w0.254: v2(97.66,84.84) C117.2 ; C117.2 98.22,85.8 97.79,86.23 R115.2 R122.2 ; C117.2 97.27,83.88 U4.41
  BOTTOM w0.254: R120.2 97.54,84.96 v2(97.66,84.84)
UNNAMED_4_ADLTC7878V2_I126_ISNSP: length 6.3
  TOP w0.254: R112.2 R118.2 96.58,87.01 C116.2 96.6,85.96 ; U4.42 96.77,84.66 C117.1 96.6,85.96 ; 96.6,85.96 96.7,85.85 v2(97.03,85.85)
  BOTTOM w0.254: C116.2 96.7,85.85 v2(97.03,85.85)
UNNAMED_4_ADLTC7878V2_I126_ITHB: length 2.4
  TOP w0.254: R110.2 98.04,74.68 97.77,74.95 U4.21
UNNAMED_4_ADLTC7878V2_I126_MODE: length 6.1
  TOP w0.254: U4.26 100.71,77.13 101.26,76.58 v2(101.79,76.58) R121.1 ; R125.1 v2(104.55,76.58)
  LAYER_6 w0.254: v2(101.79,76.58) 101.85,76.52 104.48,76.52 v2(104.55,76.58)
UNNAMED_4_ADLTC7878V2_I126_PGOOD: length 24.2
  TOP w0.254: U4.19 96.77,75.18 96.01,74.42 v2(96.01,74.17) R126.1 ; v2(78.87,71.12) TP66.1
  LAYER_6 w0.254: v2(78.87,71.12) 79.88,70.1 94.11,70.1 96.39,72.39 96.39,73.41 96.01,73.79 v2(96.01,74.17)
UNNAMED_4_ADLTC7878V2_I126_PHASMD: length 6.2
  TOP w0.254: 101.82,77.62 U4.27 ; 101.82,77.62 v2(101.79,77.6) R123.1 ; 101.82,77.62 102.08,77.62 ; R124.1 v2(104.55,77.6)
  LAYER_6 w0.254: v2(104.55,77.6) 104.48,77.66 101.85,77.66 v2(101.79,77.6)
UNNAMED_4_ADLTC7878V2_I126_SETCUR: length 3
  TOP w0.254: R119.1 102.11,80.64 101.09,79.62 U4.31
UNNAMED_4_ADLTC7878V2_I126_SW1: length 48.8
  TOP w0.254: U4.45 95.27,84.87 C115.2 ; R113.1 v1(82.55,98.17) ; C115.2 94.37,85.78 ; C115.2 93.92,85.78 93.85,85.85 v1(93.6,85.85) ; R112.1 95.07,88.19 95,88.27 v1(94.87,88.27)
  LAYER_4 w0.508: v1(93.6,85.85) 89.53,89.92 86.61,89.92 80.01,96.52 80.01,100.33 79.5,100.84 v4(78.61,100.84)
  LAYER_6 w0.254: v1(94.87,88.27) 94.87,88.65 91.82,91.69 83.95,91.69 82.93,92.71 82.93,97.79 v1(82.55,98.17)
  vias: v4(74.8,100.84) v4(74.8,99.57) v4(74.8,98.3) v4(74.8,97.03) v4(76.07,100.84) v4(76.07,99.57) v4(76.07,98.3) v4(76.07,97.03) v4(77.34,100.84) v4(77.34,99.57) v4(77.34,98.3) v4(77.34,97.03) v4(78.61,99.57) v4(78.61,98.3) v4(78.61,97.03)
UNNAMED_4_ADLTC7878V2_I126_SW2: length 52.3
  TOP w0.254: R122.1 v1(99.06,88.9) ; v1(98.68,100.33) 98.7,100.35 L4.2 ; C118.1 95.27,74.01 U4.16
  TOP w0.508: v1(94.87,73.15) 94.92,73.21 C118.1
  LAYER_4 w0.508: v1(94.87,73.15) 94.87,74.8 95.38,75.31 98.55,75.31 99.89,76.64 99.89,81.85 104.65,86.61 104.65,94.55 107.89,97.79 v4(108.58,97.79)
  LAYER_6 w0.254: v1(98.68,100.33) 96.77,98.42 96.77,94.23 98.04,92.96 98.04,90.3 99.06,89.28 v1(99.06,88.9)
  vias: v3(99.19,97.28) v3(99.19,96.52) v3(99.95,97.28) v3(99.95,96.52) v3(100.71,97.28) v3(100.71,96.52) v3(101.47,97.28) v3(101.47,96.52) v3(102.23,97.28) v3(102.23,96.52) v4(108.58,101.6) v4(108.58,100.33) v4(108.58,99.06) v4(109.86,101.6) v4(109.86,100.33) v4(109.86,99.06) v4(109.86,97.79) v4(111.12,101.6) v4(111.12,100.33) v4(111.12,99.06) v4(111.12,97.79) v4(112.39,101.6) v4(112.39,100.33) v4(112.39,99.06) v4(112.39,97.79)
UNNAMED_4_ADLTC7878V2_I126_TG1: length 30.7
  TOP w0.254: U4.47 94.27,83.4 93.85,83.82 v1(93.6,83.82)
  LAYER_4 w0.508: v1(79.88,105.03) 80.9,104.01 80.9,97.03 87,90.93 89.79,90.93 94.49,86.23 94.49,85.22 93.6,84.33 v1(93.6,83.82)
UNNAMED_4_ADLTC7878V2_I126_TG2: length 44.5
  TOP w0.254: R130.2 v1(114.05,105.03) ; v1(93.98,74.8) 94.27,75.09 U4.14
  LAYER_4 w0.508: v1(114.05,105.03) 112.01,103 108.2,103 107.19,101.98 107.19,98.42 103.76,95 103.76,87 99.06,82.3 99.06,76.96 98.3,76.2 95,76.2 93.98,75.18 v1(93.98,74.8)
UNNAMED_4_ADLTC7878V2_I126_VIN: length 3.3
  TOP w0.254: U4.4 92.08,80.62 91.19,81.51 C111.1
UNNAMED_4_ADLTC7878V2_I126_VOUT: length 19.2
  TOP w0.254: U4.38 98.77,83.53 99.19,83.95 99.19,84.84 v1(99.69,85.34) 100.08,85.34 100.13,85.29 R131.1 ; R127.2 v2(88.77,77.22)
  LAYER_4 w0.254: v1(99.69,85.34) 97.92,83.57 95.5,83.57 92.84,80.9 92.84,79.63 91.31,78.11 89.66,78.11 v2(88.77,77.22)
UNNAMED_4_CAP_I32_N1: length 1
  TOP w0.254: R111.2 C114.1
UNNAMED_4_CAP_I93_N2: length 2
  TOP w0.254: R133.1 106.68,84.26 TP64.1
UNNAMED_4_IND_I84_N1: length 41.3
  TOP w0.254: R113.2 v1(83.82,98.17) ; v1(94.36,100.33) 94.34,100.35 L4.1 ; R118.1 v1(96.52,88.77) ; R115.1 v1(97.79,88.9)
  LAYER_6 w0.254: v1(83.82,98.17) 83.44,97.79 83.44,92.96 84.2,92.2 92.08,92.2 95.5,88.77 95.5,88.2 95.82,87.88 97.22,87.88 97.79,88.46 v1(97.79,88.9) ; v1(94.36,100.33) 96.27,98.42 96.27,93.98 97.54,92.71 97.54,90.3 96.52,89.28 v1(96.52,88.77)
  vias: v3(90.68,97.28) v3(90.68,96.52) v3(91.44,97.28) v3(91.44,96.52) v3(92.2,97.28) v3(92.2,96.52) v3(92.96,97.28) v3(92.96,96.52) v3(93.73,97.28) v3(93.73,96.52)
UNNAMED_4_NCTESTPAD_I106_N1: length 5.3
  TOP w0.254: R135.2 R136.1
  TOP w0.381: R135.2 104.97,75.44 105.03,75.38 105.03,74.74 106.68,73.09 TP71.1
UNNAMED_4_RES_I64_N1: length 7.7
  TOP w0.254: 78.37,102.99 78.86,102.99 v1(79.25,103.38)
  LAYER_6 w0.508: v1(73.66,103.38) v1(79.25,103.38)
  BOTTOM w0.254: 74.53,102.99 74.05,102.99 v1(73.66,103.38)
UNNAMED_4_RES_I65_N1: length 7.8
  TOP w0.254: v1(73.15,96.14) 73.15,96.5 72.61,97.04
  LAYER_6 w0.508: v1(73.15,101.73) v1(73.15,96.14)
  BOTTOM w0.254: 72.61,100.88 72.61,101.18 v1(73.15,101.73)
UNNAMED_4_RES_I79_N1: length 7.9
  TOP w0.254: v1(113.28,95.5) 112.99,95.8 M27.4
  LAYER_6 w0.508: v1(107.57,95.5) v1(113.28,95.5)
  BOTTOM w0.254: M31.4 107.86,95.8 v1(107.57,95.5)
UNNAMED_4_RES_I108_N1: length 8.2
  TOP w0.254: M28.4 114.44,97.44 114.05,97.04 v1(114.05,96.9)
  LAYER_6 w0.508: v1(114.05,102.74) v1(114.05,96.9)
  BOTTOM w0.254: v1(114.05,102.74) 114.44,102.35 M32.4
UNNAMED_5_ADLTC7878V2_I47_BG1: length 27.7
  TOP w0.254: U5.1 92.84,21.17 v1(92.84,21.97) ; R142.2 v1(72.64,32.89)
  LAYER_4 w0.508: v1(92.84,21.97) 92.33,22.48 92.33,24.13 89.28,27.18 77.72,27.18 72.64,32.26 v1(72.64,32.89)
UNNAMED_5_ADLTC7878V2_I47_BG2: length 38.2
  TOP w0.254: 92.84,15.62 92.88,15.66 U5.12 ; R161.2 v1(106.81,32.89)
  TOP w0.381: v1(92.84,13.84) 92.84,15.62
  LAYER_4 w0.508: v1(106.81,32.89) 106.81,25.4 102.87,21.46 102.87,12.95 99.57,9.65 95.5,9.65 92.84,12.32 v1(92.84,13.84)
UNNAMED_5_ADLTC7878V2_I47_BOOST1: length 2
  TOP w0.254: C148.1 94.77,23.28 U5.46
UNNAMED_5_ADLTC7878V2_I47_BOOST2: length 2.7
  TOP w0.254: U5.15 94.77,13.67 C151.2
UNNAMED_5_ADLTC7878V2_I47_CSN: length 6.4
  TOP w0.254: TP79.1 103.76,22.8 R162.1 103.7,22.61 102.49,22.61 100.55,20.66 U5.35
UNNAMED_5_ADLTC7878V2_I47_CSP: length 2.9
  TOP w0.254: TP84.1 102.23,20.83 101.47,20.83 100.81,20.17 U5.34
UNNAMED_5_ADLTC7878V2_I47_EXTVCC: length 16.1
  TOP w0.254: TP80.1 v2(78.99,19.3) ; U5.8 90.19,17.66 C152.1
  LAYER_6 w0.254: v2(91,18.16) 88.52,18.16 87.38,19.3 v2(78.99,19.3)
UNNAMED_5_ADLTC7878V2_I47_FREQ: length 2.8
  TOP w0.254: U5.28 101.49,17.17 101.98,17.65 R150.1
UNNAMED_5_ADLTC7878V2_I47_ISNSD: length 4
  TOP w0.254: U5.43 96.27,22.73 95.76,23.24 95.76,24.38 v2(95.5,24.64) 95.5,24.96 C149.1
  BOTTOM w0.254: v2(95.5,24.64) 95.5,25.07 C149.1
UNNAMED_5_ADLTC7878V2_I47_ISNSN: length 7.3
  TOP w0.254: v2(97.66,23.88) C150.2 ; C150.2 98.22,24.84 97.79,25.27 R148.2 R155.2 ; C150.2 97.27,22.92 U5.41
  BOTTOM w0.254: v2(97.66,23.88) 97.54,24 R153.2
UNNAMED_5_ADLTC7878V2_I47_ISNSP: length 6.3
  TOP w0.254: 96.6,25 96.7,24.89 v2(97.03,24.89) ; 96.6,25 C149.2 96.58,26.05 R151.2 R145.2 ; 96.6,25 C150.1 96.77,23.7 U5.42
  BOTTOM w0.254: v2(97.03,24.89) 96.7,24.89 C149.2
UNNAMED_5_ADLTC7878V2_I47_ITHB: length 2.4
  TOP w0.254: R143.2 98.04,13.72 97.77,13.99 U5.21
UNNAMED_5_ADLTC7878V2_I47_MODE: length 6.1
  TOP w0.254: U5.26 100.71,16.17 101.26,15.62 v2(101.79,15.62) R154.1 ; R158.1 v2(104.55,15.62)
  LAYER_6 w0.254: v2(104.55,15.62) 104.48,15.56 101.85,15.56 v2(101.79,15.62)
UNNAMED_5_ADLTC7878V2_I47_PGOOD: length 25.5
  TOP w0.254: v2(78.87,10.79) TP83.1 ; R159.1 v2(96.01,13.21) 96.01,13.46 96.77,14.22 U5.19
  LAYER_6 w0.254: v2(96.01,13.21) 96.01,12.89 96.39,12.51 96.39,10.73 94.11,8.45 81.22,8.45 v2(78.87,10.79)
UNNAMED_5_ADLTC7878V2_I47_PHASMD: length 6.2
  TOP w0.254: U5.27 101.82,16.66 ; 101.82,16.66 v2(101.79,16.64) R156.1 ; 101.82,16.66 102.08,16.66 ; R157.1 v2(104.55,16.64)
  LAYER_6 w0.254: v2(101.79,16.64) 101.85,16.7 104.48,16.7 v2(104.55,16.64)
UNNAMED_5_ADLTC7878V2_I47_SETCUR: length 3
  TOP w0.254: U5.31 101.09,18.66 102.11,19.68 R152.1
UNNAMED_5_ADLTC7878V2_I47_SW1: length 48.9
  TOP w0.254: C148.2 93.92,24.82 93.85,24.89 v1(93.6,24.89) ; C148.2 95.27,23.91 U5.45 ; C148.2 94.37,24.82 ; R146.1 v1(82.55,37.21) ; R145.1 95.07,27.23 95,27.3 v1(94.87,27.3)
  LAYER_4 w0.508: v1(93.6,24.89) 89.92,28.57 87,28.57 80.01,35.56 80.01,39.37 79.5,39.88 v4(78.61,39.88)
  LAYER_6 w0.254: v1(94.87,27.3) 94.87,27.81 91.95,30.73 83.95,30.73 82.93,31.75 82.93,36.83 v1(82.55,37.21)
  vias: v4(74.8,39.88) v4(74.8,38.61) v4(74.8,37.34) v4(74.8,36.07) v4(76.07,39.88) v4(76.07,38.61) v4(76.07,37.34) v4(76.07,36.07) v4(77.34,39.88) v4(77.34,38.61) v4(77.34,37.34) v4(77.34,36.07) v4(78.61,38.61) v4(78.61,37.34) v4(78.61,36.07)
UNNAMED_5_ADLTC7878V2_I47_SW2: length 52
  TOP w0.254: L5.2 98.7,39.39 v1(98.68,39.37) ; C151.1 95.27,13.05 U5.16 ; R155.1 v1(99.06,27.94)
  TOP w0.508: v1(94.87,12.19) 94.92,12.25 C151.1
  LAYER_4 w0.508: v1(94.87,12.19) 94.87,13.84 95.5,14.48 98.17,14.48 99.89,16.19 99.89,20.89 104.65,25.65 104.65,33.59 107.89,36.83 v4(108.58,36.83)
  LAYER_6 w0.254: v1(98.68,39.37) 96.77,37.47 96.77,33.27 98.04,32 98.04,29.27 99.06,28.26 v1(99.06,27.94)
  vias: v3(99.19,36.32) v3(99.19,35.56) v3(99.95,36.32) v3(99.95,35.56) v3(100.71,36.32) v3(100.71,35.56) v3(101.47,36.32) v3(101.47,35.56) v3(102.23,36.32) v3(102.23,35.56) v4(108.58,40.64) v4(108.58,39.37) v4(108.58,38.1) v4(109.86,40.64) v4(109.86,39.37) v4(109.86,38.1) v4(109.86,36.83) v4(111.12,40.64) v4(111.12,39.37) v4(111.12,38.1) v4(111.12,36.83) v4(112.39,40.64) v4(112.39,39.37) v4(112.39,38.1) v4(112.39,36.83)
UNNAMED_5_ADLTC7878V2_I47_TG1: length 30.8
  TOP w0.254: U5.47 94.27,22.44 93.85,22.86 v1(93.6,22.86)
  LAYER_4 w0.508: v1(79.88,44.07) 80.9,43.05 80.9,36.07 87.38,29.59 90.17,29.59 94.61,25.15 94.61,24.38 93.6,23.37 v1(93.6,22.86)
UNNAMED_5_ADLTC7878V2_I47_TG2: length 44.2
  TOP w0.254: R163.2 v1(114.05,44.07) ; v1(93.98,13.84) 94.27,14.13 U5.14
  LAYER_4 w0.508: v1(93.98,13.84) 93.98,14.22 95.12,15.37 97.79,15.37 99.06,16.64 99.06,21.34 103.76,26.04 103.76,34.04 107.19,37.47 107.19,41.02 108.2,42.04 112.01,42.04 v1(114.05,44.07)
UNNAMED_5_ADLTC7878V2_I47_VIN: length 3.3
  TOP w0.254: C144.1 91.19,20.55 92.08,19.66 U5.4
UNNAMED_5_ADLTC7878V2_I47_VOUT: length 19.2
  TOP w0.254: R160.2 v2(88.77,16.26) ; U5.38 98.77,22.57 99.19,22.99 99.19,23.88 v1(99.69,24.38) 100.08,24.38 100.13,24.33 R164.1
  LAYER_4 w0.254: v2(88.77,16.26) 89.41,16.89 91.06,16.89 92.84,18.67 92.84,20.07 95.38,22.61 97.92,22.61 v1(99.69,24.38)
UNNAMED_5_CAP_I33_N1: length 1
  TOP w0.254: R144.2 C147.1
UNNAMED_5_CAP_I94_N2: length 2
  TOP w0.254: TP81.1 106.68,23.3 R166.1
UNNAMED_5_IND_I85_N1: length 41.2
  TOP w0.254: R146.2 v1(83.82,37.21) ; R151.1 v1(96.52,27.81) ; L5.1 94.34,39.39 v1(94.36,39.37) ; R148.1 v1(97.79,27.94)
  LAYER_6 w0.254: v1(97.79,27.94) 97.79,27.43 97.41,27.05 95.89,27.05 95.57,27.37 95.57,27.88 92.2,31.24 84.2,31.24 83.44,32 83.44,36.83 v1(83.82,37.21) ; v1(96.52,27.81) 96.52,28.26 97.54,29.27 97.54,31.75 96.27,33.02 96.27,37.47 v1(94.36,39.37)
  vias: v3(90.68,36.32) v3(90.68,35.56) v3(91.44,36.32) v3(91.44,35.56) v3(92.2,36.32) v3(92.2,35.56) v3(92.96,36.32) v3(92.96,35.56) v3(93.73,36.32) v3(93.73,35.56)
UNNAMED_5_NCTESTPAD_I107_N1: length 5.3
  TOP w0.254: R168.2 R169.1
  TOP w0.381: R168.2 104.97,14.48 105.03,14.42 105.03,13.78 106.68,12.13 TP88.1
UNNAMED_5_RES_I65_N1: length 7.7
  TOP w0.254: v1(79.25,42.42) 78.86,42.03 78.37,42.03
  LAYER_6 w0.508: v1(73.66,42.42) v1(79.25,42.42)
  BOTTOM w0.254: 74.53,42.03 74.05,42.03 v1(73.66,42.42)
UNNAMED_5_RES_I66_N1: length 7.8
  TOP w0.254: 72.61,36.08 73.15,35.54 v1(73.15,35.18)
  LAYER_6 w0.508: v1(73.15,40.77) v1(73.15,35.18)
  BOTTOM w0.254: 72.61,39.92 72.61,40.22 v1(73.15,40.77)
UNNAMED_5_RES_I80_N1: length 7.9
  TOP w0.254: v1(113.28,34.54) 112.99,34.84 M35.4
  LAYER_6 w0.508: v1(107.57,34.54) v1(113.28,34.54)
  BOTTOM w0.254: v1(107.57,34.54) 107.86,34.84 M39.4
UNNAMED_5_RES_I109_N1: length 8.2
  TOP w0.254: v1(114.05,35.94) 114.05,36.08 114.44,36.48 M36.4
  LAYER_6 w0.508: v1(114.05,41.78) v1(114.05,35.94)
  BOTTOM w0.254: M40.4 114.44,41.39 v1(114.05,41.78)
UNNAMED_6_ADLT3014V2_I44_SHDNN: length 7.9
  TOP w0.254: U6.3 135.23,126.56 134.71,126.04 JP4.2
UNNAMED_6_ADLTC6909_I1_MOD: length 20.5
  TOP w0.254: U7.14 132.39,135.39 v2(132.4,135.38)
  LAYER_6 w0.254: v2(132.4,135.38) 130.87,136.91 123.19,136.91 120.68,139.42 JP5.7
  BOTTOM w0.254: JP5.1 JP5.3 JP5.5 JP5.7
UNNAMED_6_ADLTC6909_I1_PH0: length 22.6
  TOP w0.254: v2(134.75,135.38) 134.76,135.39 U7.3
  LAYER_6 w0.254: JP1.2 141.6,145.32 141.6,135.51 138.68,132.59 136.14,132.59 134.75,133.99 v2(134.75,135.38)
UNNAMED_6_ADLTC6909_I1_PH1: length 13.9
  TOP w0.254: v2(137.54,136.65) 136.78,135.89 U7.4
  LAYER_6 w0.254: v2(137.54,136.65) 138.18,136.65 139.06,137.54 139.06,144.69 JP2.2
UNNAMED_6_ADLTC6909_I1_PH2: length 15.2
  TOP w0.254: U7.15 v2(130.24,134.89)
  LAYER_4 w0.254: JP3.2 130.3,146.59 128.78,145.07 128.78,136.36 v2(130.24,134.89)
  LAYER_6 w0.254: 130.28,134.89 v2(130.24,134.89)
UNNAMED_6_ADLTC6909_I1_SET: length 2.7
  TOP w0.254: R187.2 132.53,134.05 132.18,134.39 U7.16
UNNAMED_6_CAP_I32_N1: length 2.5
  TOP w0.254: JP5.4 125.07,143.42 C175.1
VAUX: length 54.6
  TOP w0.254: R187.1 134.43,134.17 134.65,134.39 U7.1 ; C173.1 129.35,135.89 129.49,135.89 ; v1(136.4,123.57) 136.47,123.64 R188.1
  TOP w0.305: C173.1 129.48,135.89 129.49,135.89 U7.13
  LAYER_5 w0.254: v1(136.4,123.57) 138.43,125.6 138.43,126.36 v1(140.46,128.4)
  LAYER_6 w0.254: v1(136.78,133.86) 136.14,134.49 136.14,138.3 133.6,140.84 127.22,140.84 JP5.2
  BOTTOM w0.254: JP1.1 JP2.1 JP3.1 127.76,148.59 124.59,145.41 JP5.2
VFB_1: length 23.3
  TOP w0.254: v2(115.44,257.18) TP18.1 R5.1 ; v2(101.79,257.43) R36.1 R35.2 101.6,258.44 100.54,259.5 U1.25
  LAYER_6 w0.254: v2(101.79,257.43) 102.93,256.29 114.55,256.29 v2(115.44,257.18)
VFB_2: length 98.1
  TOP w0.254: v2(101.79,196.47) R66.1 R65.2 101.6,197.49 100.54,198.54 U2.25 ; v2(115.44,196.22) TP43.1 R175.1 ; R5.2 v2(121.16,257.18)
  LAYER_5 w0.254: v2(121.16,257.18) 121.16,254.38 119,252.22 119,247.14 131.7,234.44 131.7,212.47 v2(115.44,196.22)
  LAYER_6 w0.254: v2(101.79,196.47) 102.81,195.45 107.82,195.45 109.09,196.72 114.94,196.72 v2(115.44,196.22)
VFB_3: length 101.8
  TOP w0.254: R180.1 TP52.1 v2(115.44,135.25) ; U3.25 100.54,137.58 101.6,136.53 R103.2 R104.1 v2(101.79,135.51) ; R175.2 v2(121.16,196.22)
  LAYER_5 w0.254: v2(115.44,135.25) 115.44,145.67 119,149.22 126.24,149.22 131.7,154.69 131.7,172.97 119,185.67 119,191.13 121.16,193.29 v2(121.16,196.22)
  LAYER_6 w0.254: v2(101.79,135.51) 102.68,134.62 114.81,134.62 v2(115.44,135.25)
VFB_4: length 97.6
  TOP w0.254: R185.1 TP69.1 v2(115.44,74.3) ; v2(101.79,74.55) R137.1 R136.2 101.6,75.56 100.54,76.62 U4.25 ; R180.2 v2(121.16,135.25)
  LAYER_5 w0.254: v2(115.44,74.3) 115.44,75.44 131.7,91.69 131.7,111.76 119,124.46 119,125.98 119.89,126.87 119.89,133.99 v2(121.16,135.25)
  LAYER_6 w0.254: v2(115.44,74.3) 114.68,73.53 102.81,73.53 v2(101.79,74.55)
VFB_5: length 93.3
  TOP w0.254: U5.25 100.54,15.66 101.6,14.61 R169.2 R170.1 v2(101.79,13.59) ; R185.2 v2(121.16,74.3) ; TP86.1 v2(115.44,15.24)
  LAYER_5 w0.254: v2(115.44,15.24) 115.7,15.24 131.7,31.24 131.7,50.8 119.13,63.37 119.13,65.66 120.14,66.67 120.14,69.85 121.16,70.87 v2(121.16,74.3)
  LAYER_6 w0.254: v2(101.79,13.59) 102.74,12.64 106.17,12.64 108.78,15.24 v2(115.44,15.24)
VOUT: length 698.5
  TOP w0.254: R134.1 129.26,98.71 v1(129.29,98.68) ; TP19.1 v1(110.36,254.63) ; v1(100.84,147.45) 100.77,147.38 R98.2 ; v1(129.29,159.64) 129.26,159.67 R101.1 ; TP44.1 v1(110.36,193.68) ; v1(130.81,37.72) 130.84,37.75 R167.2 ; R131.2 100.77,86.42 v1(100.84,86.49) ; R164.2 100.77,25.46 v1(100.84,25.53) ; v1(129.29,220.6) 128.48,220.6 R63.1 ; v1(129.29,37.72) 129.26,37.75 R167.1 ; R101.2 130.84,159.67 v1(130.81,159.64) ; R33.2 130.84,281.59 v1(130.81,281.56) ; v1(130.81,98.68) 131.62,98.68 R134.2 ; R68.2 100.77,208.34 v1(100.84,208.41) ; v1(100.84,269.37) 100.77,269.3 R71.2 ; TP70.1 v1(110.36,71.75) ; v1(130.81,220.6) 130.84,220.63 R63.2 ; TP87.1 v1(110.36,10.79) ; TP53.1 v1(110.36,132.72) ; R33.1 129.26,281.59 v1(129.29,281.56)
  TOP w0.381: R168.1 106.55,14.61 TP87.1 ; R135.1 106.55,75.56 TP70.1 ; TP53.1 106.55,136.53 R102.1 ; TP44.1 106.55,197.49 R64.1 ; TP19.1 106.55,258.44 R34.1
  TOP w0.508: R166.2 v1(106.62,21.53) ; R133.2 v1(106.62,82.49) ; R165.2 v1(105.54,20.7) ; R132.2 v1(105.54,81.66) ; R99.2 v1(105.54,142.62) ; v1(106.55,143.45) 106.55,143.45 R100.2 ; v1(106.55,204.41) 106.55,204.41 R62.2 ; R31.2 v1(105.54,264.54) ; R61.2 v1(105.54,203.58) ; R32.2 v1(106.62,265.37)
  LAYER_3 w0.381: v1(135.89,218.44) v1(135.38,218.44) ; v1(135.38,218.44) v1(134.87,218.44) ; v1(135.38,218.44) 135.38,216.53 116.33,197.49 114.17,197.49 v1(110.36,193.68) ; v1(135.76,279.4) v1(135.25,279.4) ; v1(135.25,279.4) 135.25,278.38 123.19,266.32 120.14,266.32 110.36,256.54 v1(110.36,254.63) ; v1(135.25,279.4) v1(134.75,279.4) ; v1(134.87,96.52) v1(135.38,96.52) ; v1(135.38,96.52) 135.38,93.73 117.22,75.56 112.27,75.56 110.36,73.66 v1(110.36,71.75) ; v1(135.38,96.52) v1(135.89,96.52) ; v1(135.38,35.56) v1(135.89,35.56) ; v1(135.38,35.56) 135.38,32.51 115.57,12.7 112.27,12.7 v1(110.36,10.79) ; v1(135.38,35.56) v1(134.87,35.56) ; v1(135.89,157.35) v1(135.38,157.35) ; v1(135.38,157.35) v1(134.87,157.35) ; v1(135.38,157.35) 135.38,156.46 129.16,150.24 122.17,150.24 110.36,138.43 v1(110.36,132.72)
  LAYER_6 w0.254: v1(129.29,98.68) 129.74,98.23 129.74,93.16 122.43,85.85 108.84,85.85 105.54,82.55 v1(105.54,81.66) ; v1(106.62,265.37) 106.62,265.88 111.12,270.38 124.59,270.38 130.36,276.16 130.36,281.11 v1(130.81,281.56) ; v1(129.29,37.72) 129.74,37.27 129.74,32.45 122.43,25.15 108.97,25.15 105.54,21.72 v1(105.54,20.7) ; v1(118.62,216.41) 115.19,216.41 111.51,212.72 104.58,212.72 100.84,208.98 v1(100.84,208.41) ; v1(130.81,98.68) 130.36,98.23 130.36,93.02 122.68,85.34 109.09,85.34 106.62,82.88 v1(106.62,82.49) ; v1(105.54,203.58) 105.54,204.79 109.03,208.28 122.17,208.28 129.74,215.84 129.74,220.15 v1(129.29,220.6) ; v1(100.84,25.53) 105.16,29.84 111.51,29.84 115.19,33.53 v1(118.62,33.53) ; v1(100.84,269.37) 100.84,269.88 104.65,273.69 111.51,273.69 115.19,277.37 v1(118.62,277.37) ; v1(106.55,204.41) 106.55,204.98 109.35,207.77 122.43,207.77 130.36,215.7 130.36,220.15 v1(130.81,220.6) ; v1(129.29,159.64) 129.74,159.19 129.74,155.52 125.35,151.13 115.06,151.13 111,147.07 108.97,147.07 105.54,143.64 v1(105.54,142.62) ; v1(118.62,94.49) 115.19,94.49 111.51,90.81 105.16,90.81 v1(100.84,86.49) ; v1(100.84,147.45) 100.84,149.35 103.25,151.76 105.92,151.76 108.97,154.81 113.92,154.81 114.55,155.45 v1(118.62,155.45) ; v1(105.54,264.54) 105.98,264.99 105.98,266 110.87,270.89 124.33,270.89 129.74,276.29 129.74,281.11 v1(129.29,281.56) ; v1(130.81,37.72) 130.36,37.27 130.36,32.32 122.68,24.64 109.22,24.64 106.62,22.04 v1(106.62,21.53) ; v1(106.55,143.45) 106.55,143.89 109.22,146.56 111.25,146.56 115.32,150.62 125.6,150.62 130.36,155.38 130.36,159.19 v1(130.81,159.64)
  BOTTOM w0.508: R192.1 v1(129.29,159.64) ; R193.2 v1(130.81,98.68) ; R190.1 v1(129.29,281.56) ; R192.2 v1(130.81,159.64) ; R193.1 v1(129.29,98.68) ; R194.1 v1(129.29,37.72) ; R190.2 v1(130.81,281.56) ; R194.2 v1(130.81,37.72) ; R191.1 v1(129.29,220.6) ; R191.2 v1(130.81,220.6)
  vias: v1(115.32,279.53) v1(115.32,218.57) v1(115.32,157.61) v1(115.32,96.65) v1(115.32,35.69) v1(115.82,279.53) v1(115.82,218.57) v1(115.82,157.61) v1(115.82,96.65) v1(115.82,35.69) v1(116.33,279.53) v1(116.33,218.57) v1(116.33,157.61) v1(116.33,96.65) v1(116.33,35.69) v1(118.11,279.53) v1(118.11,218.57) v1(118.11,157.61) v1(118.11,96.65) v1(118.11,35.69) v1(118.62,279.53) v1(118.62,218.57) v1(118.62,157.61) v1(118.62,96.65) v1(118.62,35.69) v1(119.13,279.53) v1(119.13,218.57) v1(119.13,157.61) v1(119.13,96.65) v1(119.13,35.69) v1(121.41,279.53) v1(121.41,218.57) v1(121.41,157.61) v1(121.41,96.65) v1(121.41,35.69) v1(121.92,279.53) v1(121.92,218.57) v1(121.92,157.61) v1(121.92,96.65) v1(121.92,35.69) v1(122.43,279.53) v1(122.43,218.57) v1(122.43,157.61) v1(122.43,96.65) v1(122.43,35.69) v1(124.71,279.53) v1(124.71,218.57) v1(124.71,157.61) v1(124.71,96.65) v1(124.71,35.69) v1(125.22,279.53) v1(125.22,218.57) v1(125.22,157.61) v1(125.22,96.65) v1(125.22,35.69) v1(125.73,279.53) v1(125.73,218.57) v1(125.73,157.61) v1(125.73,96.65) v1(125.73,35.69) v1(138.18,279.4) v1(138.3,218.44) v1(138.43,157.35) v1(138.43,96.52) v1(138.43,35.56) v1(138.68,279.4) v1(138.81,218.44) v1(138.94,157.35) v1(138.94,96.52) v1(138.94,35.56) v1(139.19,279.4) v1(139.32,218.44) v1(139.45,157.35) v1(139.45,96.52) v1(139.45,35.56) v1(140.97,106.68) v1(140.97,101.6) v1(140.97,97.79) v1(142.24,289.56) v1(142.24,284.48) v1(142.24,279.4) v1(142.24,228.6) v1(142.24,223.52) v1(142.24,218.44) v1(142.24,167.64) v1(142.24,162.56) v1(142.24,157.48) v1(142.24,45.72) v1(142.24,40.64) v1(142.24,35.56) v1(147.32,279.4) v1(147.32,274.32) v1(147.32,269.24) v1(147.32,264.16) v1(147.32,259.08) v1(147.32,248.92) v1(147.32,238.76) v1(147.32,233.68) v1(147.32,228.6) v1(147.32,223.52) v1(147.32,218.44) v1(147.32,213.36) v1(147.32,208.28) v1(147.32,203.2) v1(147.32,187.96) v1(147.32,177.8) v1(147.32,172.72) v1(147.32,167.64) v1(147.32,162.56) v1(147.32,157.48) v1(147.32,152.4) v1(147.32,147.32) v1(147.32,142.24) v1(147.32,137.16) v1(147.32,127) v1(147.32,116.84) v1(147.32,111.76) v1(147.32,106.68) v1(147.32,101.6) v1(147.32,96.52) v1(147.32,91.44) v1(147.32,81.28) v1(147.32,66.04) v1(147.32,55.88) v1(147.32,50.8) v1(147.32,45.72) v1(147.32,40.64) v1(147.32,35.56) v1(152.4,289.56) v1(152.4,284.48) v1(152.4,279.4) v1(152.4,274.32) v1(152.4,269.24) v1(152.4,264.16) v1(152.4,259.08) v1(152.4,248.92) v1(152.4,238.76) v1(152.4,233.68) v1(152.4,228.6) v1(152.4,223.52) v1(152.4,218.44) v1(152.4,213.36) v1(152.4,208.28) v1(152.4,203.2) v1(152.4,198.12) v1(152.4,187.96) v1(152.4,177.8) v1(152.4,172.72) v1(152.4,167.64) v1(152.4,162.56) v1(152.4,157.48) v1(152.4,152.4) v1(152.4,147.32) v1(152.4,142.24) v1(152.4,137.16) v1(152.4,127) v1(152.4,116.84) v1(152.4,111.76) v1(152.4,106.68) v1(152.4,101.6) v1(152.4,96.52) v1(152.4,91.44) v1(152.4,86.36) v1(152.4,81.28) v1(152.4,76.2) v1(152.4,71.12) v1(152.4,66.04) v1(152.4,55.88) v1(152.4,50.8) v1(152.4,45.72) v1(152.4,40.64) v1(152.4,35.56) v1(157.48,284.48) v1(157.48,279.4) v1(157.48,274.32) v1(157.48,269.24) v1(157.48,264.16) v1(157.48,259.08) v1(157.48,254) v1(157.48,248.92) v1(157.48,243.84) v1(157.48,238.76) v1(157.48,233.68) v1(157.48,228.6) v1(157.48,223.52) v1(157.48,218.44) v1(157.48,213.36) v1(157.48,208.28) v1(157.48,203.2) v1(157.48,198.12) v1(157.48,193.04) v1(157.48,187.96) v1(157.48,182.88) v1(157.48,177.8) v1(157.48,172.72) v1(157.48,167.64) v1(157.48,162.56) v1(157.48,157.48) v1(157.48,152.4) v1(157.48,147.32) v1(157.48,142.24) v1(157.48,137.16) v1(157.48,132.08) v1(157.48,127) v1(157.48,121.92) v1(157.48,116.84) v1(157.48,111.76) v1(157.48,106.68) v1(157.48,101.6) v1(157.48,96.52) v1(157.48,91.44) v1(157.48,86.36) v1(157.48,81.28) v1(157.48,74.93) v1(157.48,71.12) v1(157.48,66.04) v1(157.48,60.96) v1(157.48,55.88) v1(157.48,50.8) v1(157.48,45.72) v1(157.48,40.64) v1(157.48,35.56) v1(162.56,284.48) v1(162.56,279.4) v1(162.56,274.32) v1(162.56,269.24) v1(162.56,264.16) v1(162.56,259.08) v1(162.56,254) v1(162.56,248.92) v1(162.56,243.84) v1(162.56,238.76) v1(162.56,233.68) v1(162.56,228.6) v1(162.56,223.52) v1(162.56,218.44) v1(162.56,213.36) v1(162.56,208.28) v1(162.56,203.2) v1(162.56,198.12) v1(162.56,193.04) v1(162.56,187.96) v1(162.56,182.88) v1(162.56,177.8) v1(162.56,172.72) v1(162.56,167.64) v1(162.56,162.56) v1(162.56,157.48) v1(162.56,152.4) v1(162.56,147.32) v1(162.56,142.24) v1(162.56,137.16) v1(162.56,132.08) v1(162.56,127) v1(162.56,121.92) v1(162.56,116.84) v1(162.56,111.76) v1(162.56,106.68) v1(162.56,101.6) v1(162.56,96.52) v1(162.56,91.44) v1(162.56,86.36) v1(162.56,81.28) v1(162.56,76.2) v1(162.56,69.85) v1(162.56,66.04) v1(162.56,60.96) v1(162.56,55.88) v1(162.56,50.8) v1(162.56,45.72) v1(162.56,40.64) v1(162.56,35.56) v1(167.64,289.56) v1(167.64,284.48) v1(167.64,279.4) v1(167.64,274.32) v1(167.64,269.24) v1(167.64,264.16) v1(167.64,259.08) v1(167.64,254) v1(167.64,248.92) v1(167.64,243.84) v1(167.64,238.76) v1(167.64,233.68) v1(167.64,228.6) v1(167.64,223.52) v1(167.64,218.44) v1(167.64,213.36) v1(167.64,208.28) v1(167.64,203.2) v1(167.64,198.12) v1(167.64,193.04) v1(167.64,187.96) v1(167.64,182.88) v1(167.64,177.8) v1(167.64,172.72) v1(167.64,167.64) v1(167.64,162.56) v1(167.64,157.48) v1(167.64,152.4) v1(167.64,147.32) v1(167.64,142.24) v1(167.64,137.16) v1(167.64,132.08) v1(167.64,127) v1(167.64,121.92) v1(167.64,116.84) v1(167.64,111.76) v1(167.64,106.68) v1(167.64,101.6) v1(167.64,96.52) v1(167.64,91.44) v1(167.64,86.36) v1(167.64,81.28) v1(167.64,76.2) v1(167.64,71.12) v1(167.64,64.77) v1(167.64,60.96) v1(167.64,55.88) v1(167.64,50.8) v1(167.64,45.72) v1(167.64,40.64) v1(167.64,35.56) v1(172.72,198.12) v1(172.72,193.04) v1(172.72,177.8) v1(172.72,172.72) v1(172.72,157.48) v1(172.72,152.4) v1(177.8,198.12) v1(177.8,193.04) v1(177.8,177.8) v1(177.8,172.72) v1(177.8,157.48) v1(177.8,152.4) v3(124.21,289.56) v3(124.21,287.78) v3(124.21,286) v3(124.21,228.6) v3(124.21,226.82) v3(124.21,225.04) v3(124.21,167.64) v3(124.21,165.86) v3(124.21,164.08) v3(124.21,106.68) v3(124.21,105.03) v3(124.21,103.12) v3(124.21,45.72) v3(124.21,43.94) v3(124.21,42.16) v3(127.25,289.56) v3(127.25,287.78) v3(127.25,286) v3(127.25,228.6) v3(127.25,226.82) v3(127.25,225.04) v3(127.25,167.64) v3(127.25,165.86) v3(127.25,164.08) v3(127.25,106.68) v3(127.25,105.03) v3(127.25,103.12) v3(127.25,45.72) v3(127.25,43.94) v3(127.25,42.16) v3(135.64,289.56) v3(135.64,287.78) v3(135.64,286) v3(135.64,284.23) v3(135.64,283.34) v3(135.64,282.45) v3(135.64,281.56) v3(135.64,228.6) v3(135.64,226.82) v3(135.64,225.04) v3(135.64,223.14) v3(135.64,222.25) v3(135.64,221.36) v3(135.64,220.47) v3(135.64,167.64) v3(135.64,165.86) v3(135.64,164.08) v3(135.64,162.05) v3(135.64,161.16) v3(135.64,160.27) v3(135.64,159.38) v3(135.64,106.68) v3(135.64,104.9) v3(135.64,103.12) v3(135.64,100.97) v3(135.64,100.08) v3(135.64,99.19) v3(135.64,98.3) v3(135.64,45.72) v3(135.64,43.94) v3(135.64,42.16) v3(135.64,40.26) v3(135.64,39.37) v3(135.64,38.48) v3(135.64,37.59) v3(138.68,289.56) v3(138.68,287.78) v3(138.68,286) v3(138.68,284.1) v3(138.68,283.21) v3(138.68,282.32) v3(138.68,281.43) v3(138.68,228.6) v3(138.68,226.82) v3(138.68,225.04) v3(138.68,223.14) v3(138.68,222.25) v3(138.68,221.36) v3(138.68,220.47) v3(138.68,167.64) v3(138.68,165.86) v3(138.68,164.08) v3(138.68,162.05) v3(138.68,161.16) v3(138.68,160.27) v3(138.68,159.38) v3(138.68,106.68) v3(138.68,104.9) v3(138.68,103.12) v3(138.68,100.97) v3(138.68,100.08) v3(138.68,99.19) v3(138.68,98.3) v3(138.68,45.72) v3(138.68,43.94) v3(138.68,42.16) v3(138.81,40.13) v3(138.81,39.24) v3(138.81,38.35) v3(138.81,37.47) v3(147.07,289.31) v3(147.07,287.53) v3(147.07,285.75) v3(147.45,196.47) v3(147.45,193.42) v3(147.45,185.04) v3(147.45,181.99) v3(147.45,135.51) v3(147.45,132.46) v3(147.45,124.08) v3(147.45,121.03) v3(147.45,75.18) v3(147.45,72.14) v3(147.45,63.75) v3(147.45,60.71) v3(147.57,257.3) v3(147.57,254.25) v3(147.57,246) v3(147.57,242.95) v3(148.84,121.03) v3(149.22,196.47) v3(149.22,193.42) v3(149.22,185.04) v3(149.22,181.99) v3(149.22,135.51) v3(149.22,132.46) v3(149.22,75.18) v3(149.22,72.14) v3(149.22,63.75) v3(149.22,60.71) v3(149.35,257.3) v3(149.35,254.25) v3(149.35,246) v3(149.35,242.95) v3(150.11,289.31) v3(150.11,287.53) v3(150.11,285.75) v3(150.24,124.08) v3(150.24,121.03) v3(151,196.47) v3(151,193.42) v3(151,185.04) v3(151,181.99) v3(151,135.51) v3(151,132.46) v3(151,75.18) v3(151,72.14) v3(151,63.75) v3(151,60.71) v3(151.13,257.3) v3(151.13,254.25) v3(151.13,246) v3(151.13,242.95) v3(151.76,122.56) v3(158.5,289.31) v3(158.5,287.53) v3(158.5,285.75) v3(161.54,289.31) v3(161.54,287.53) v3(161.54,285.75) v4(116.46,284.48) v4(116.46,283.21) v4(116.46,281.94) v4(116.46,280.67) v4(116.46,223.52) v4(116.46,222.25) v4(116.46,220.98) v4(116.46,219.71) v4(116.46,162.56) v4(116.46,161.29) v4(116.46,160.02) v4(116.46,158.75) v4(116.46,101.6) v4(116.46,100.33) v4(116.46,99.06) v4(116.46,97.79) v4(116.46,40.64) v4(116.46,39.37) v4(116.46,38.1) v4(116.46,36.83) v4(117.73,284.48) v4(117.73,283.21) v4(117.73,281.94) v4(117.73,280.67) v4(117.73,223.52) v4(117.73,222.25) v4(117.73,220.98) v4(117.73,219.71) v4(117.73,162.56) v4(117.73,161.29) v4(117.73,160.02) v4(117.73,158.75) v4(117.73,101.6) v4(117.73,100.33) v4(117.73,99.06) v4(117.73,97.79) v4(117.73,40.64) v4(117.73,39.37) v4(117.73,38.1) v4(117.73,36.83) v4(119,284.48) v4(119,283.21) v4(119,281.94) v4(119,280.67) v4(119,223.52) v4(119,222.25) v4(119,220.98) v4(119,219.71) v4(119,162.56) v4(119,161.29) v4(119,160.02) v4(119,158.75) v4(119,101.6) v4(119,100.33) v4(119,99.06) v4(119,97.79) v4(119,40.64) v4(119,39.37) v4(119,38.1) v4(119,36.83) v4(120.27,284.48) v4(120.27,283.21) v4(120.27,281.94) v4(120.27,280.67) v4(120.27,223.52) v4(120.27,222.25) v4(120.27,220.98) v4(120.27,219.71) v4(120.27,162.56) v4(120.27,161.29) v4(120.27,160.02) v4(120.27,158.75) v4(120.27,101.6) v4(120.27,100.33) v4(120.27,99.06) v4(120.27,97.79) v4(120.27,40.64) v4(120.27,39.37) v4(120.27,38.1) v4(120.27,36.83)
